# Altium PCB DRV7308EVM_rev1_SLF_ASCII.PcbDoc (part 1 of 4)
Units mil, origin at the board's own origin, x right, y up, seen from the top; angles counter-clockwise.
Board outline 6187 x 6000 mil, 4 copper layers (Top Layer, Ground, Power, Bottom Layer), stack 61.2 mil thick; 306 components, 128 nets, 676 pads, 1026 vias.
Unrouted connection lines stored in the file: 208.
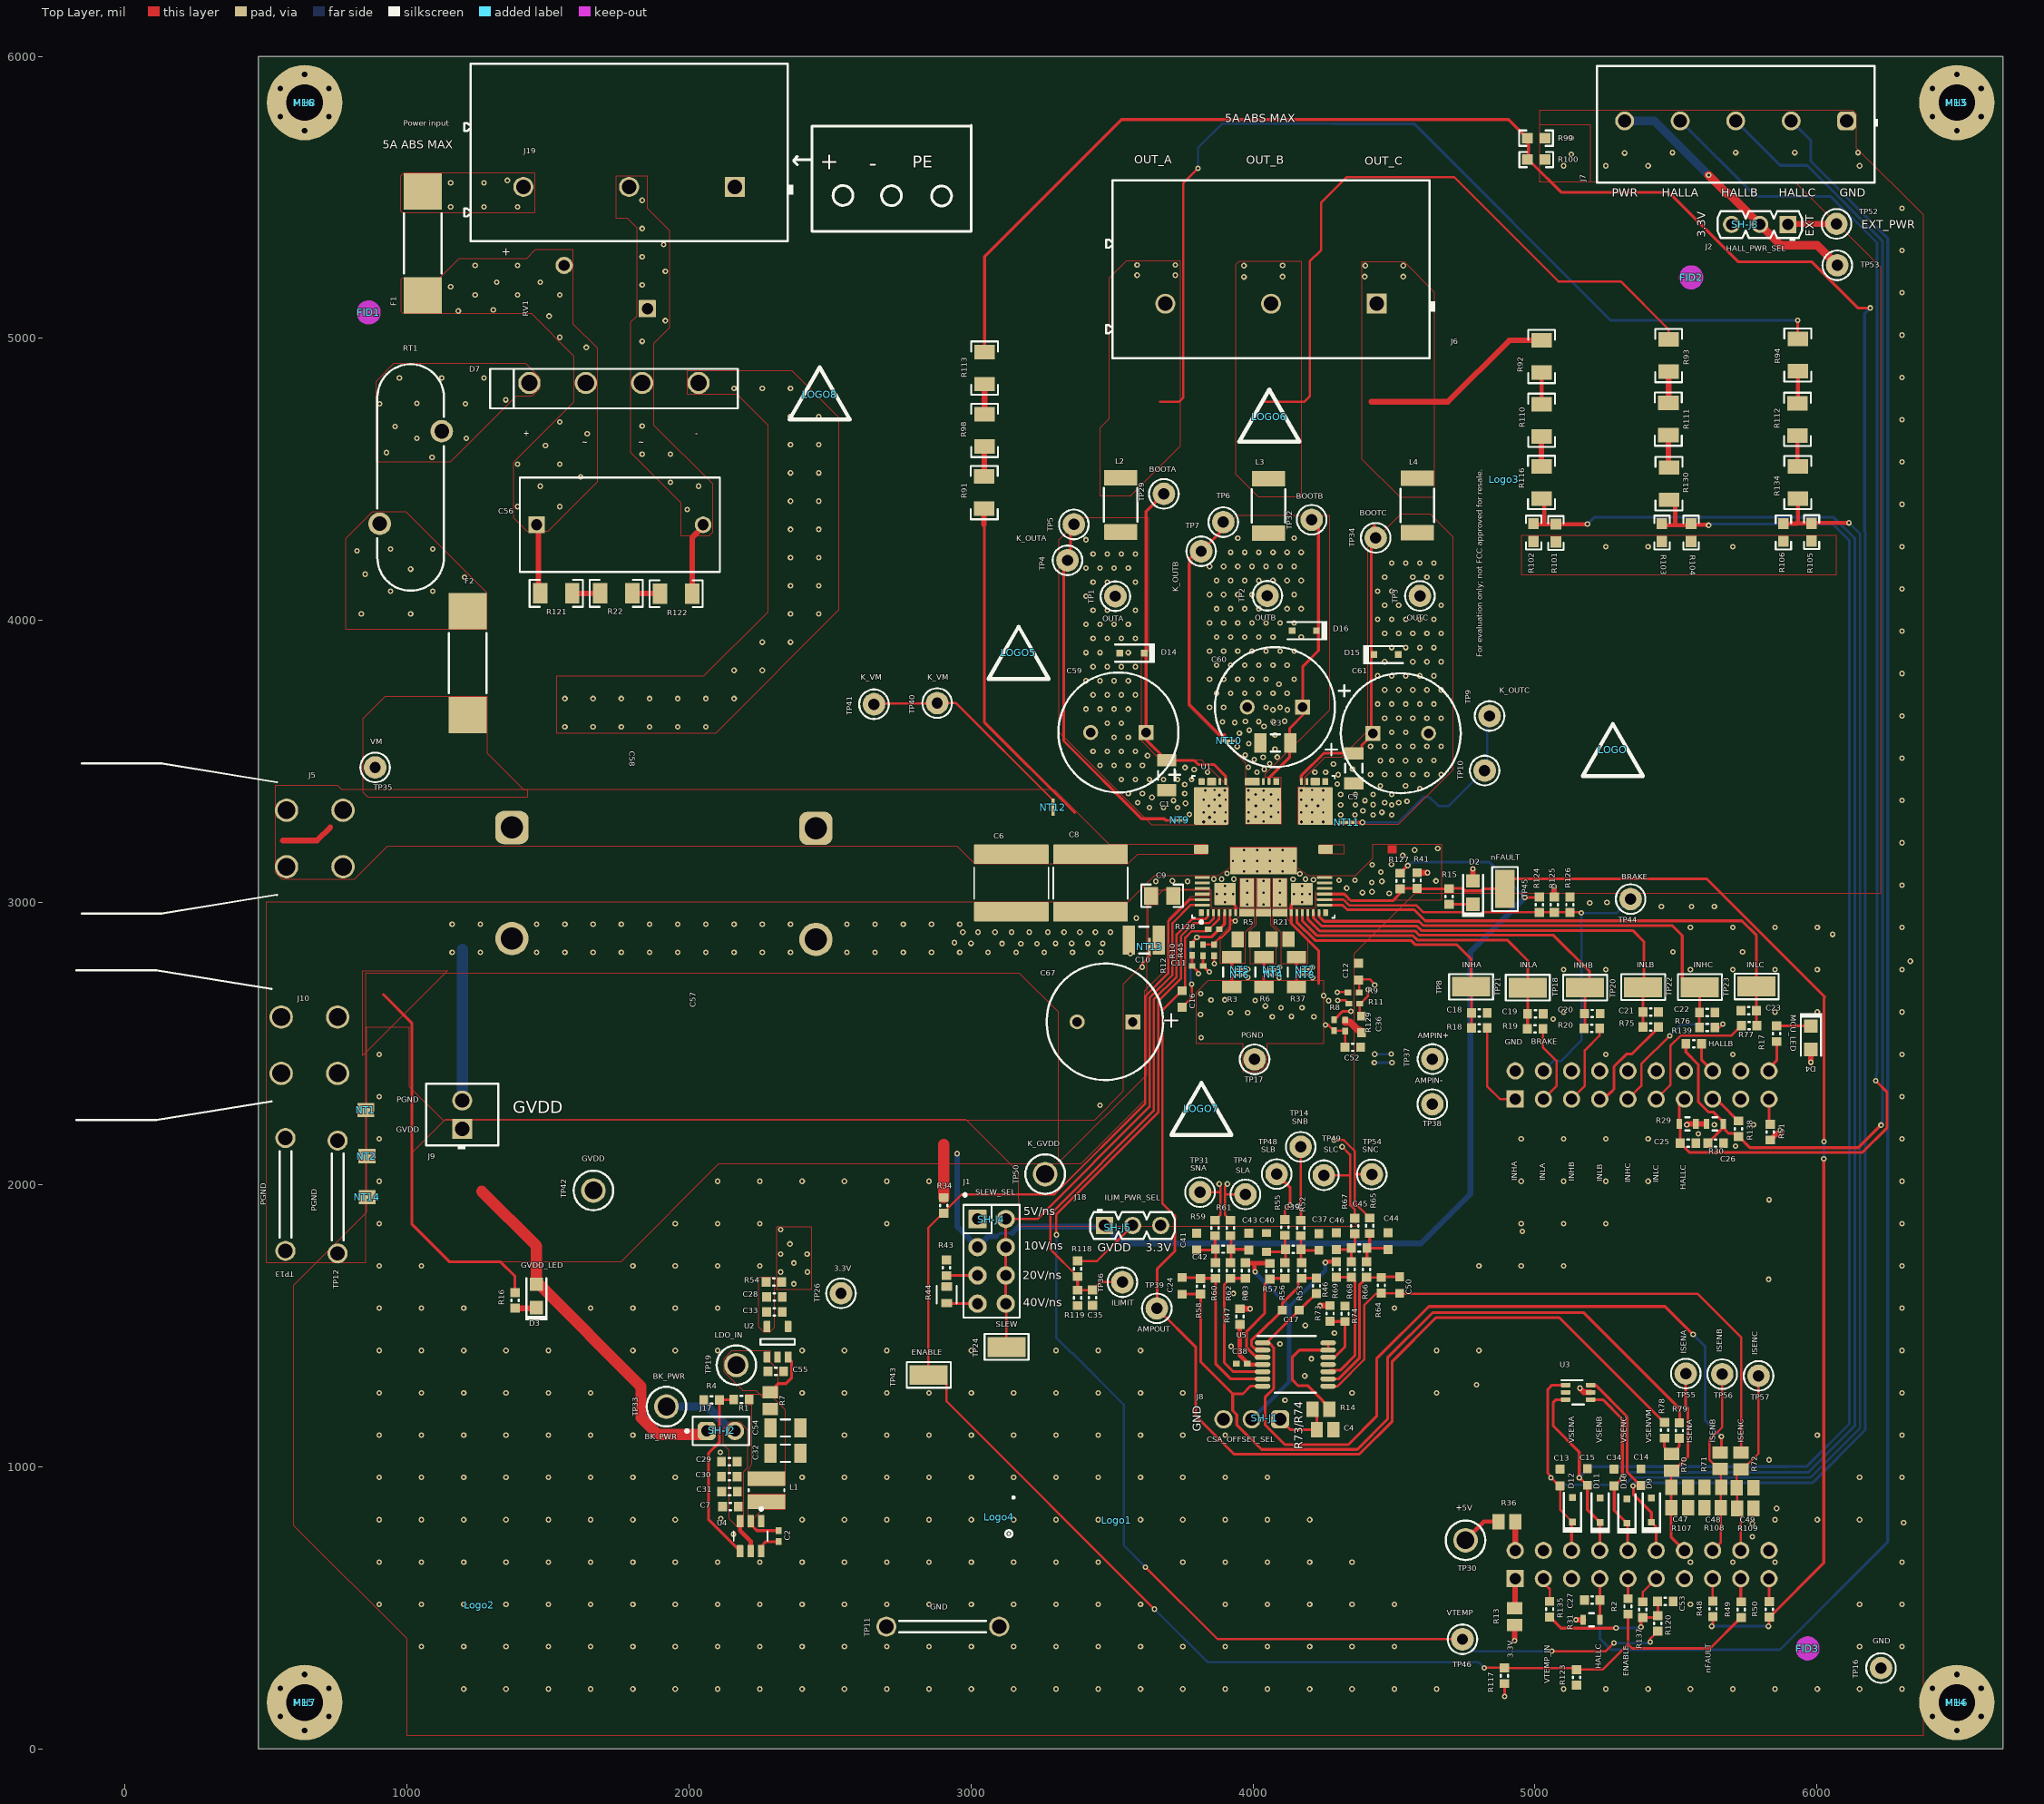
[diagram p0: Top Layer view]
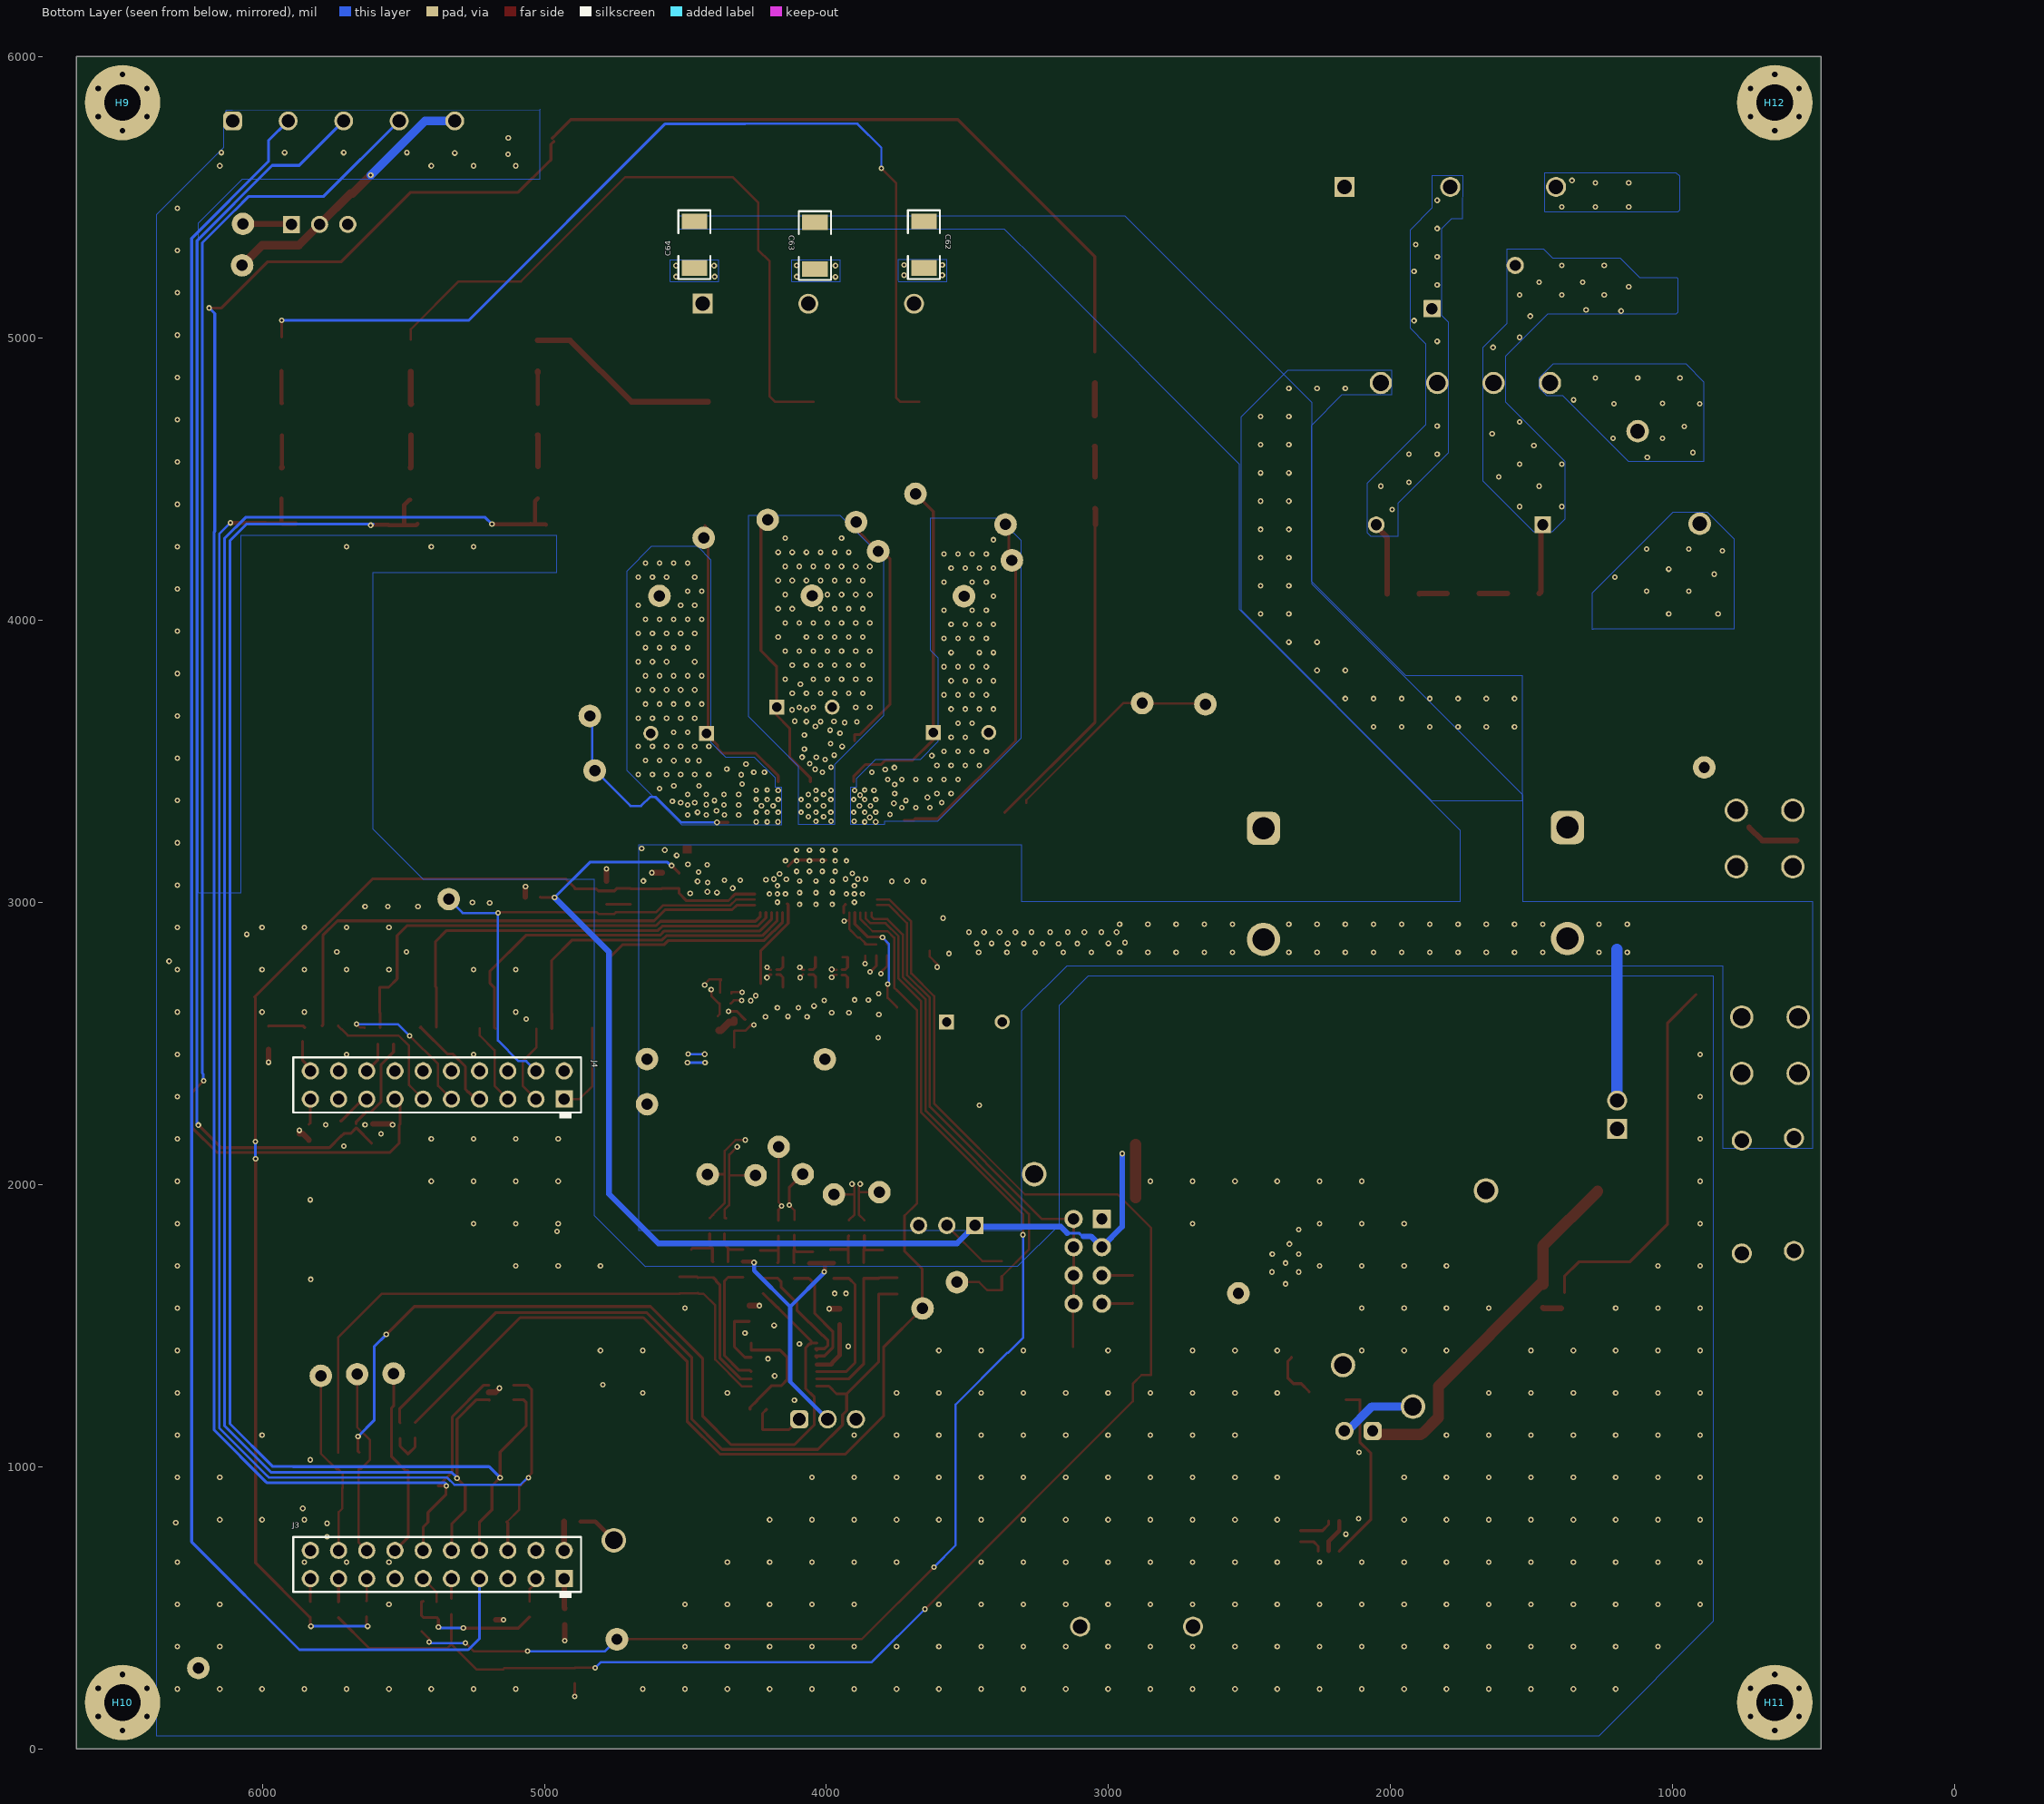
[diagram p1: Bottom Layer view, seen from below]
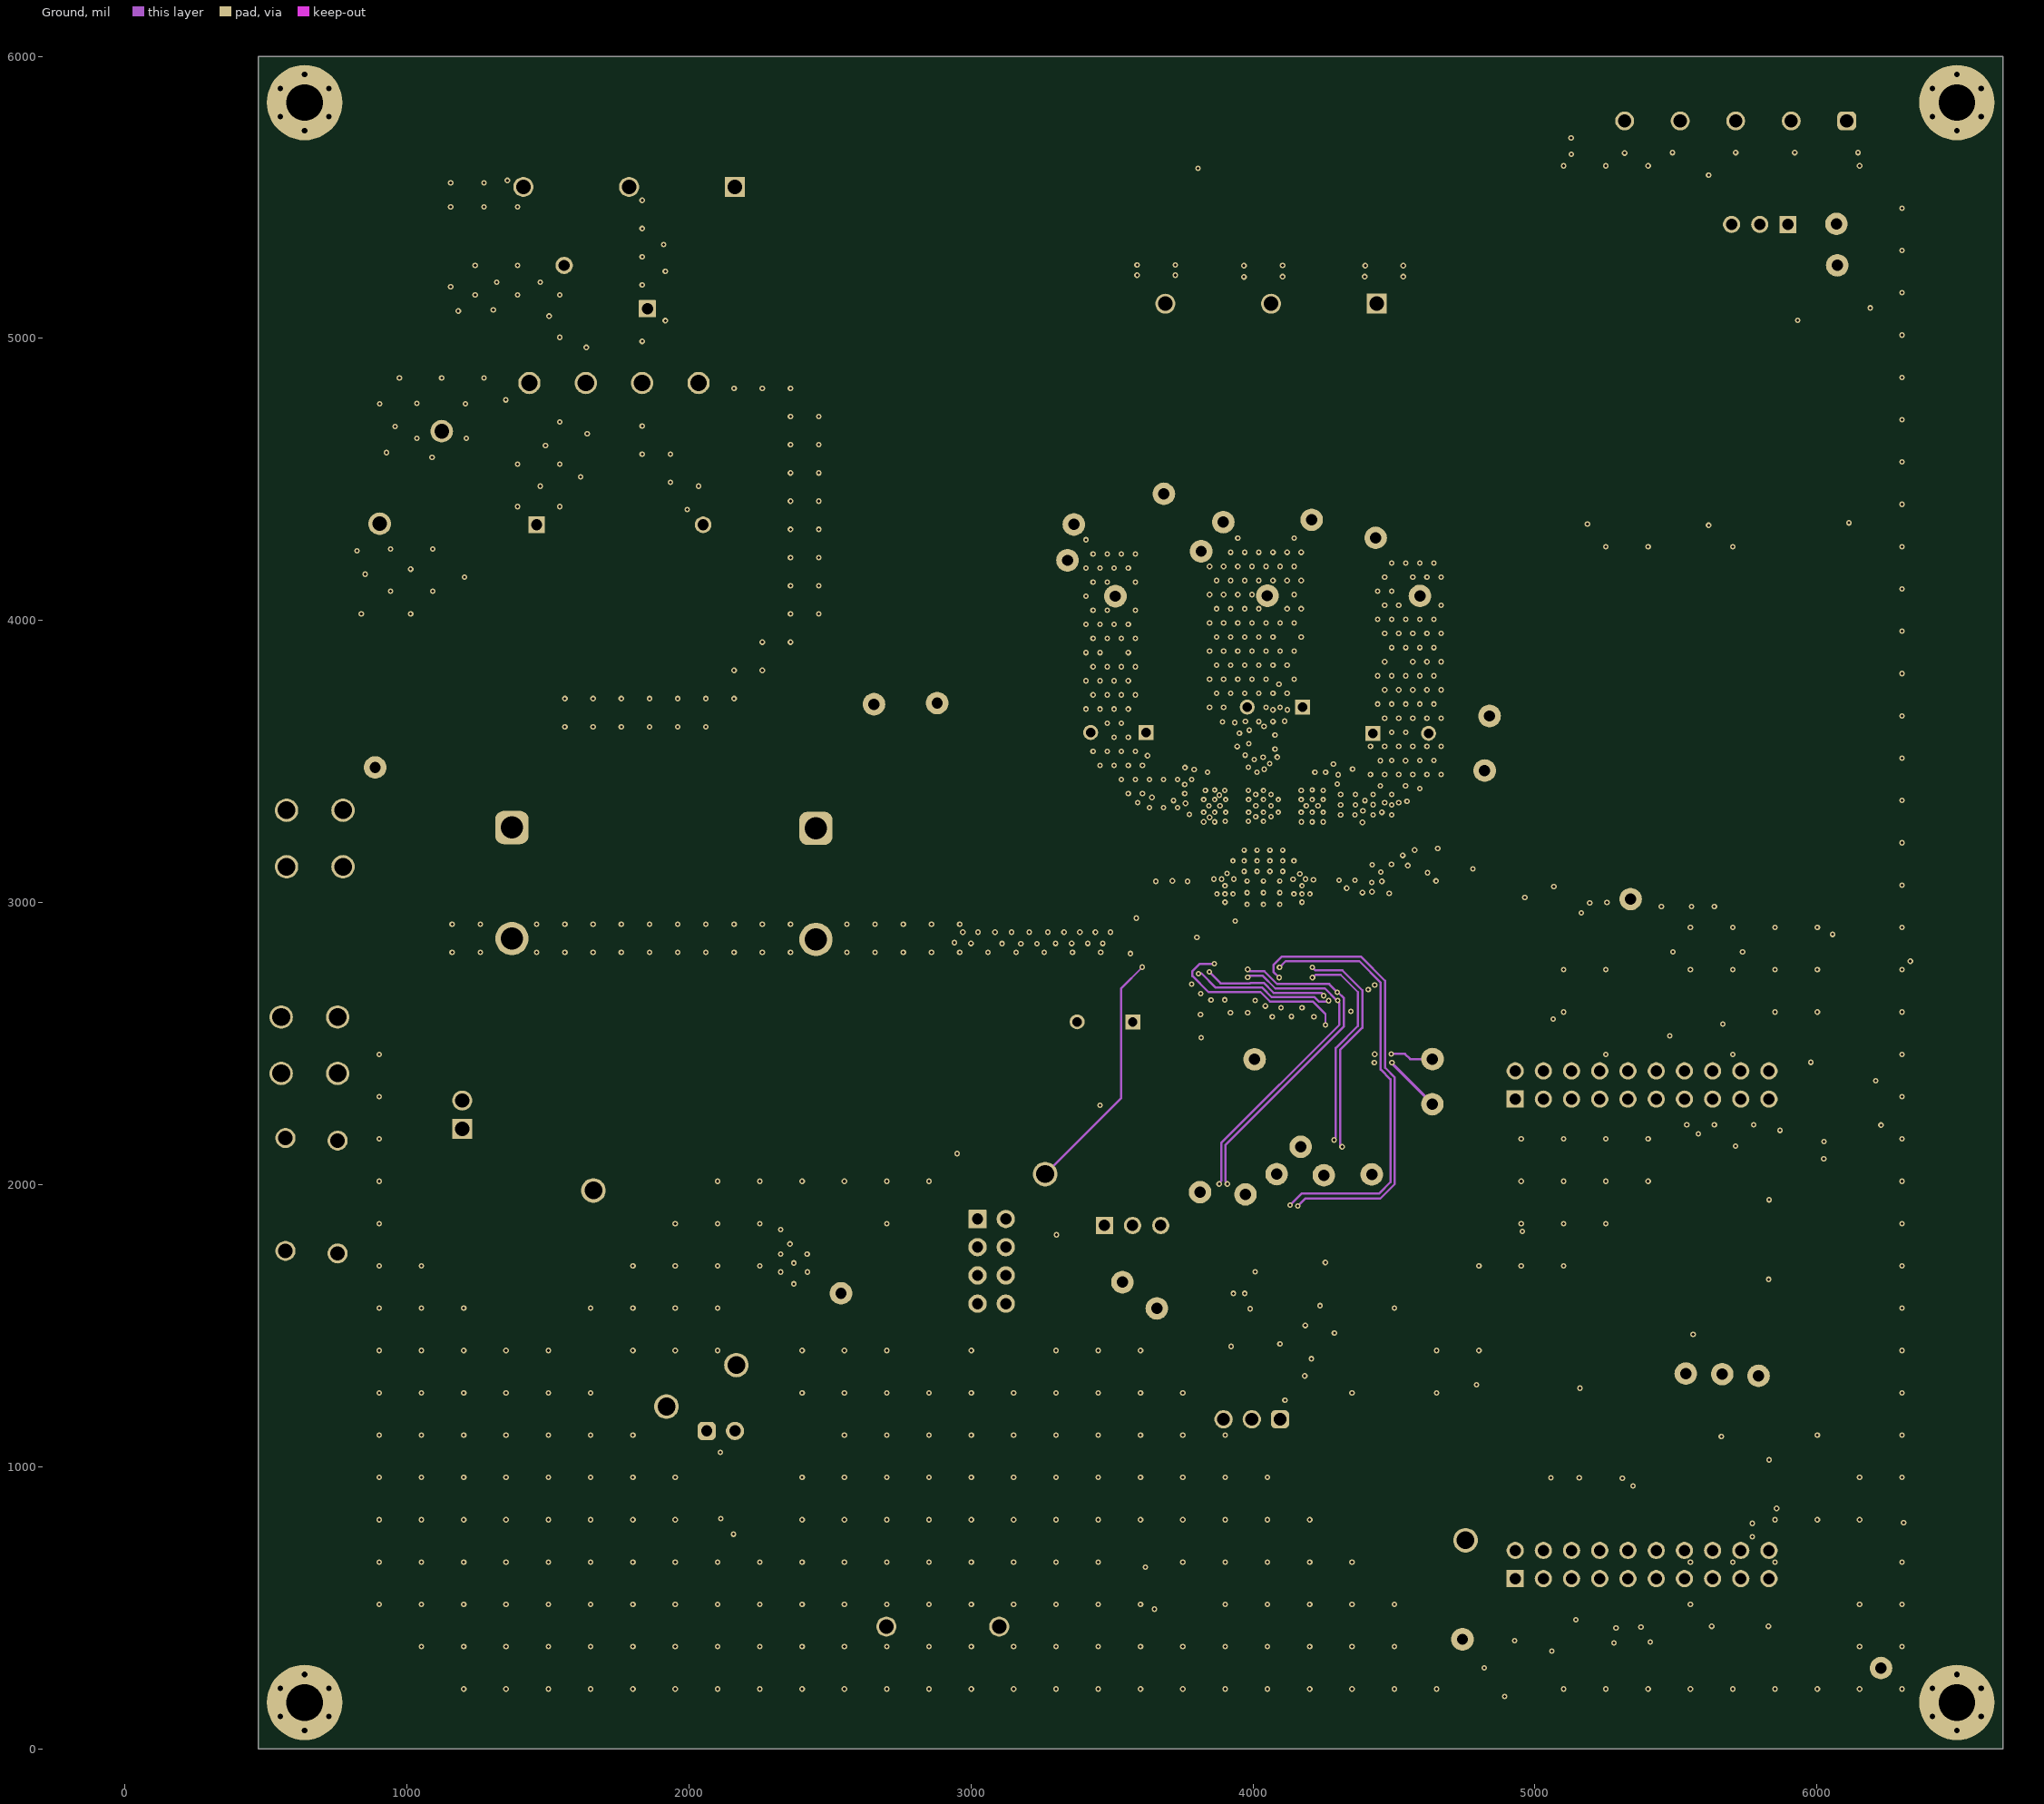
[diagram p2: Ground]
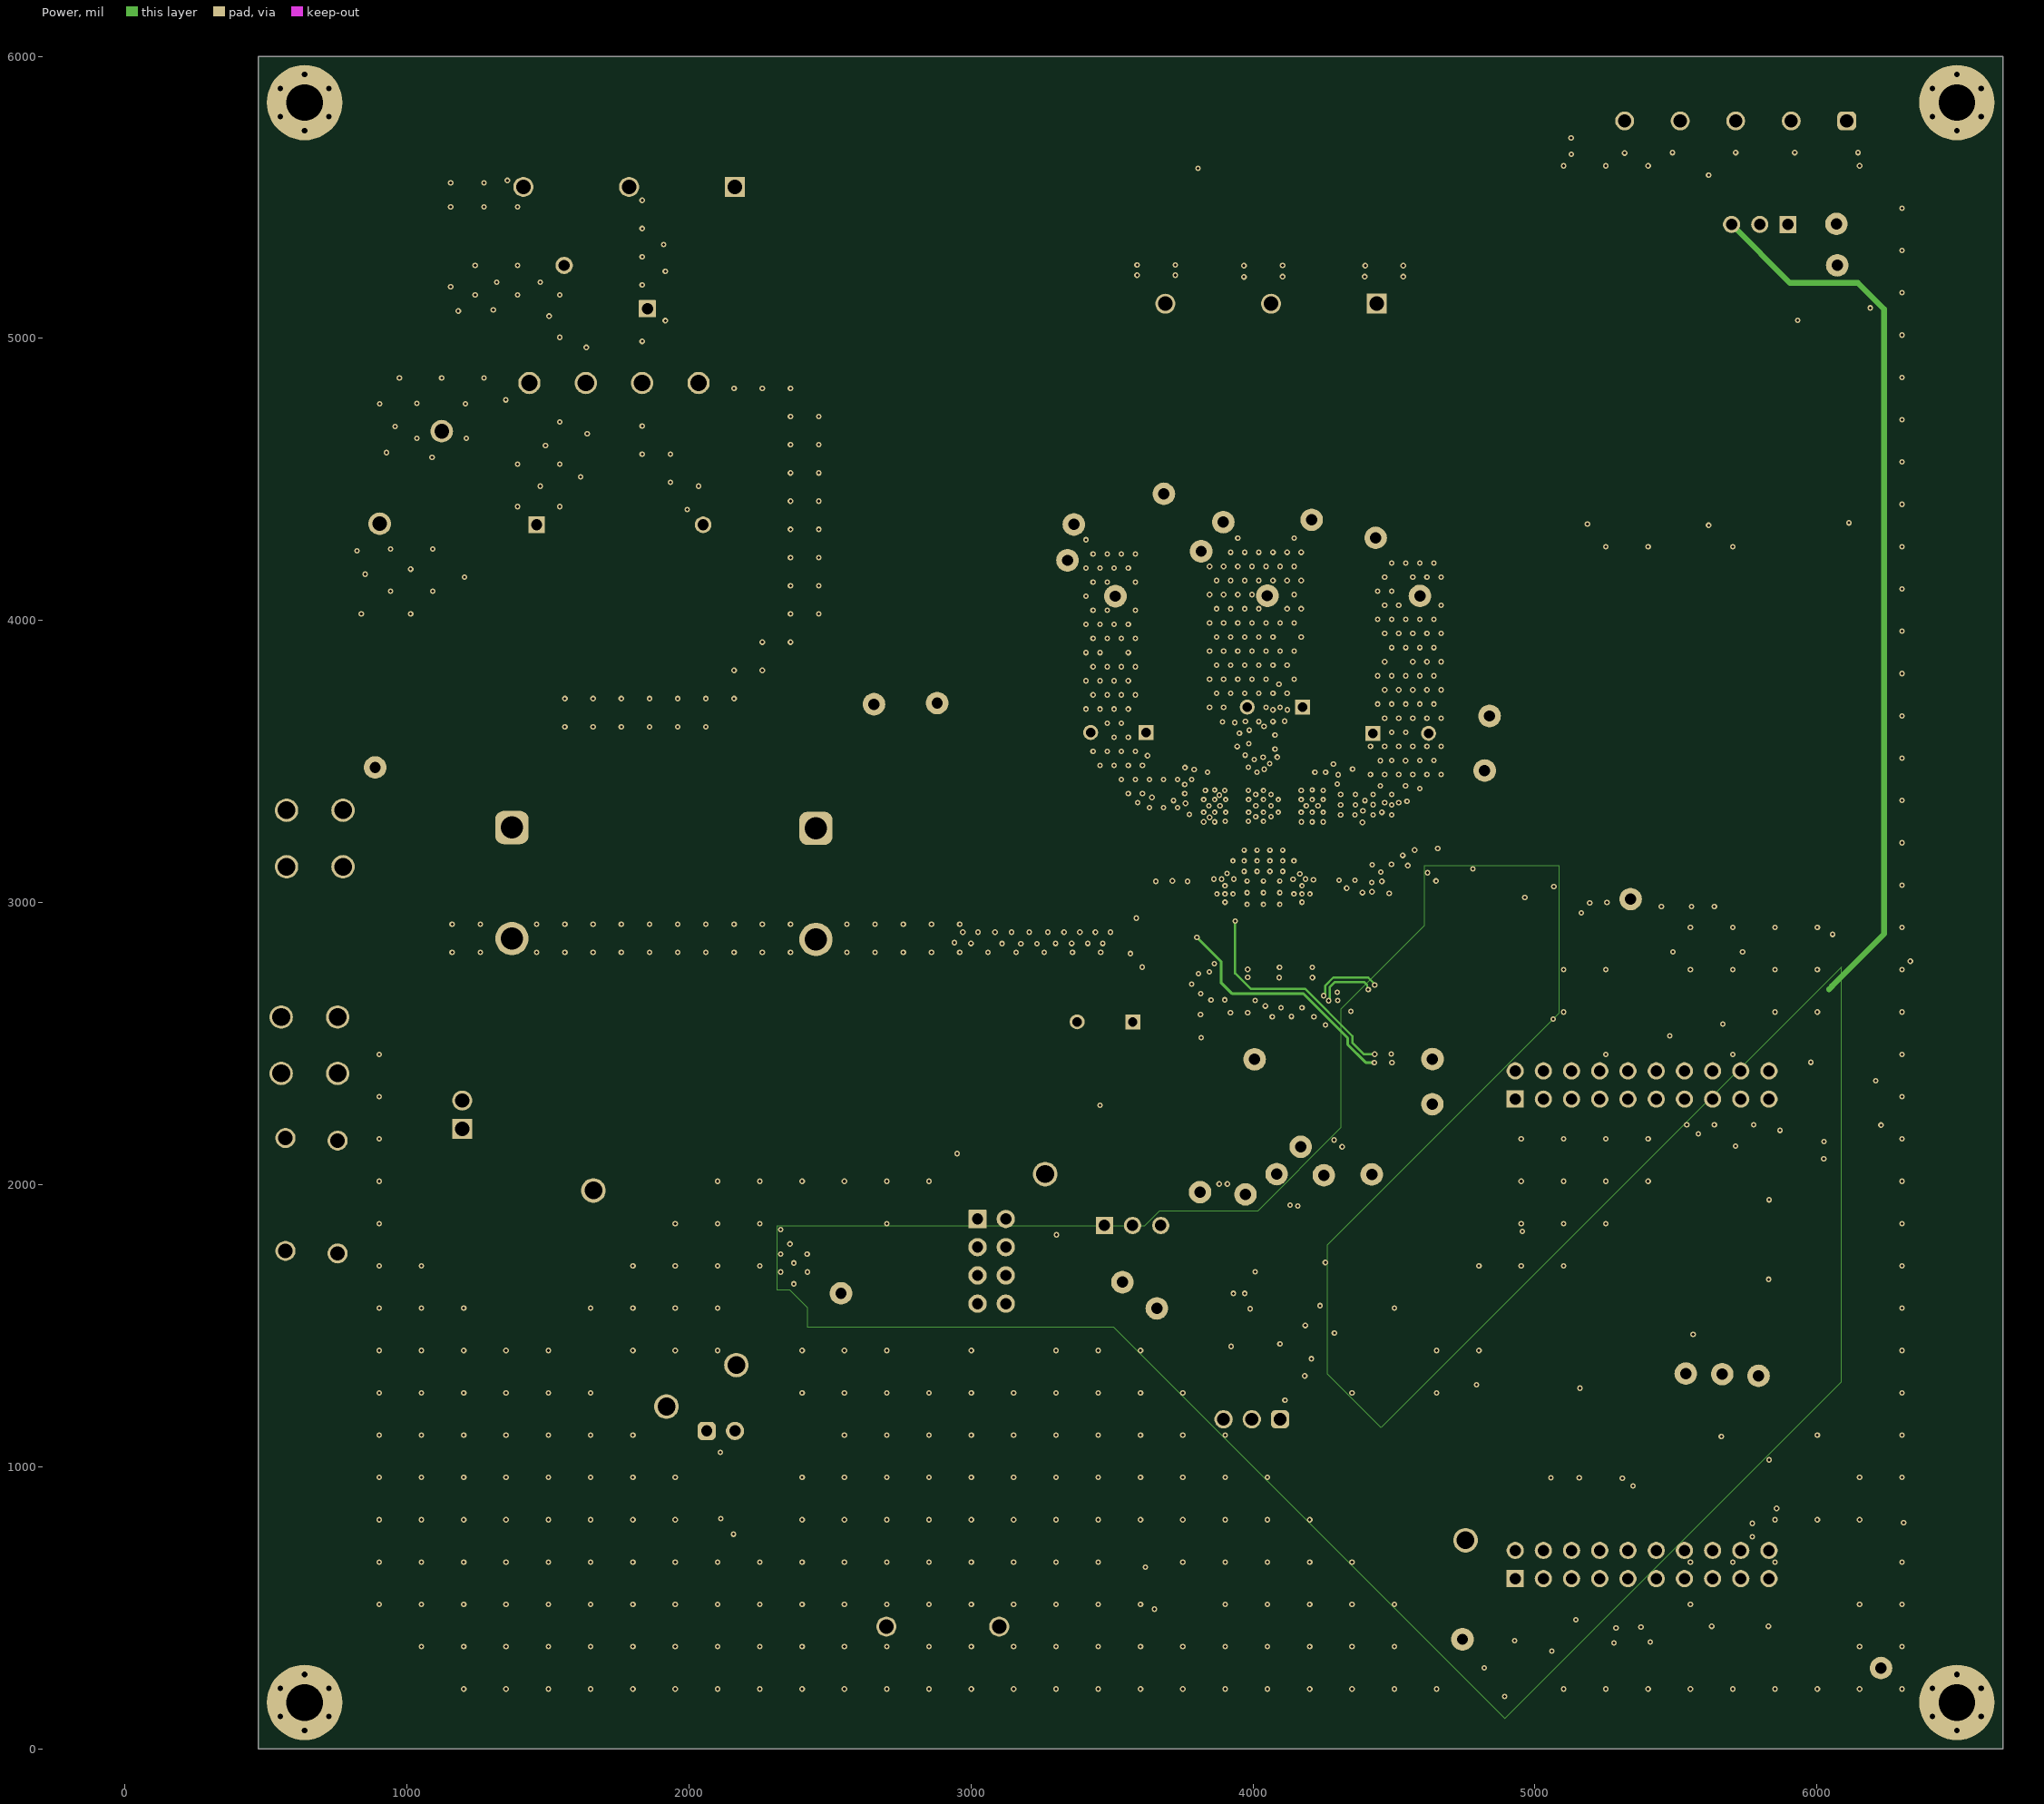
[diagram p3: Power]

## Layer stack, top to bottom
Top Solder: solder mask 0.4, Solder Resist, Dk 3.5
Top Layer: signal copper 4.2
Dielectric 1: prepreg 8, FR-4 High Tg, Dk 4.2
Ground: signal copper 1.4
Dielectric 2: core 34, FR-4 High Tg, Dk 4.2
Power: signal copper 1.4
Dielectric 3: prepreg 8, FR-4 High Tg, Dk 4.2
Bottom Layer: signal copper 4.2
Bottom Solder: solder mask 0.4, Solder Resist, Dk 3.5

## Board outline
473,0 6660,0 6660,6000 473,6000

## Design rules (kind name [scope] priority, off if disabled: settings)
AcuteAngle [All] p0: scope1count=1 scope1_0_kind=Board scope1_0_value=Board scope2count=1 scope2_0_kind=Board scope2_0_value=Board commentlength=0 minimum=4.50000000000000E+0001
AcuteAngle [All] p1: minimum=4.50000000000000E+0001 checktracksonly=FALSE
AssemblyTestPointUsage [All] p0: scope1count=1 scope1_0_kind=Board scope1_0_value=Board scope2count=1 scope2_0_kind=Board scope2_0_value=Board commentlength=0
AssemblyTestPointUsage [All] p1: valid=2
AssemblyTestpoint [All] p0: scope1count=1 scope1_0_kind=Board scope1_0_value=Board scope2count=1 scope2_0_kind=Board scope2_0_value=Board commentlength=0
BoardOutlineClearance [All] p0 off: scope1count=1 scope1_0_kind=Board scope1_0_value=Board scope2count=1 scope2_0_kind=Board scope2_0_value=Board commentlength=172 gap=30 // Protel DXP Scope 1 Expression Was: OnCopper and Not InComponentClass('Logo') and not InComponentClass('FiducialMark') and not InRegion(1000,500,4000,800) and not InPoly
BoardOutlineClearance BoardOutlineClearance_Poly [All] p0 off: scope1count=1 scope1_0_kind=Board scope1_0_value=Board scope2count=1 scope2_0_kind=Board scope2_0_value=Board commentlength=58 gap=25 // Protel DXP Scope 1 Expression Was: OnCopper and IsPoly
BoardOutlineClearance BoardOutlineClearance_MountingHoles [All] p0 off: scope1count=1 scope1_0_kind=Board scope1_0_value=Board scope2count=1 scope2_0_kind=Board scope2_0_value=Board commentlength=86 gap=39.37 // Protel DXP Scope 1 Expression Was: OnCopper and InComponentClass('Mounting Holes')
BoardOutlineClearance BoardOutlineClearance_MountingHoles [OnCopper and InComponentClass('Mounting Holes')] p1: gap=39.37 ignorepadtopadclearanceinfootprint=FALSE
BoardOutlineClearance BoardOutlineClearance_Poly [OnCopper and IsPoly] p2: gap=25 ignorepadtopadclearanceinfootprint=FALSE
BoardOutlineClearance [OnCopper and Not InComponentClass('Logo') and not InComponentClass('FiducialMark') and not InRegion(1000,500,4000,800) and not InPoly] p3: gap=30 ignorepadtopadclearanceinfootprint=FALSE
Clearance Clearance_4 [All] p0: scope1count=1 scope1_0_kind=NetClass scope1_0_value="All Nets" scope2count=1 scope2_0_kind=Layer scope2_0_value=MID1 commentlength=0 gap=7.46
Clearance Clearance_3 [All] p0 off: scope1count=1 scope1_0_kind=Board scope1_0_value=Board scope2count=1 scope2_0_kind=Board scope2_0_value=Board commentlength=76 gap=10 // Protel DXP Scope 1 Expression Was: InNamedPolygon('TOP_LAYER_OUTB_P018')
Clearance Clearance_2 [All] p0: scope1count=1 scope1_0_kind=NetClass scope1_0_value="All Nets" scope2count=1 scope2_0_kind=Layer scope2_0_value=BOTTOM commentlength=0 gap=9
Clearance Clearance_1 [All] p0: scope1count=1 scope1_0_kind=NetClass scope1_0_value="All Nets" scope2count=1 scope2_0_kind=Layer scope2_0_value=MID2 commentlength=0 gap=7.46
Clearance "Stitching AGND" [All] p0 off: scope1count=1 scope1_0_kind=Board scope1_0_value=Board scope2count=1 scope2_0_kind=Board scope2_0_value=Board commentlength=80 gap=70 // Protel DXP Scope 2 Expression Was: (IsVia and (Not IsStitchingVia)) Or IsPad
Clearance [All] p0: scope1count=1 scope1_0_kind=NetClass scope1_0_value="All Nets" scope2count=1 scope2_0_kind=Layer scope2_0_value=TOP commentlength=0 gap=7
Clearance Clearance_FiducialMark [All] p0 off: scope1count=1 scope1_0_kind=Board scope1_0_value=Board scope2count=1 scope2_0_kind=Board scope2_0_value=Board commentlength=81 gap=0 // Protel DXP Scope 2 Expression Was: IsPad and InComponentClass('FiducialMark')
Clearance Clearance_Poly [All] p0 off: scope1count=1 scope1_0_kind=Board scope1_0_value=Board scope2count=1 scope2_0_kind=Board scope2_0_value=Board commentlength=48 gap=5 // Protel DXP Scope 1 Expression Was: InPolygon
Clearance Clearance_Keepouts [All] p0 off: scope1count=1 scope1_0_kind=Board scope1_0_value=Board scope2count=1 scope2_0_kind=Board scope2_0_value=Board commentlength=99 gap=7 // Protel DXP Scope 2 Expression Was: ((IsTrack Or IsArc) And Not InPoly) And IsFree and IsKeepOut
Clearance Clearance_3 [InNamedPolygon('TOP_LAYER_OUTB_P018')] p1: gap=10 ignorepadtopadclearanceinfootprint=TRUE except(0: Arc-Hole Track-Hole SMDPad-Hole THPad-Hole Via-Hole Fill-Hole Poly-Hole Region-Hole Text-Hole)
Clearance "Stitching AGND" [IsStitchingVia and InNet('AGND') vs (IsVia and (Not IsStitchingVia)) Or IsPad] p2: gap=70 ignorepadtopadclearanceinfootprint=TRUE
Clearance Clearance_Keepouts [((IsTrack Or IsArc) And Not InPoly) And IsFree and IsKeepOut vs ((IsTrack Or IsArc) And Not InPoly) And IsFree and IsKeepOut] p3: gap=7 ignorepadtopadclearanceinfootprint=TRUE
Clearance Clearance_Poly [InPolygon] p4: gap=5 ignorepadtopadclearanceinfootprint=TRUE except(7: Fill-Fill Fill-Poly Fill-Region Poly-Poly Poly-Region Region-Region)
Clearance Clearance_FiducialMark [IsKeepOut and InComponentClass('FiducialMark') vs IsPad and InComponentClass('FiducialMark')] p5: gap=0 ignorepadtopadclearanceinfootprint=FALSE
Clearance [InNetClass('All Nets') vs OnLayer('Top Layer')] p6: gap=7 ignorepadtopadclearanceinfootprint=TRUE
Clearance Clearance_2 [InNetClass('All Nets') vs OnLayer('Bottom Layer')] p7: gap=9 ignorepadtopadclearanceinfootprint=TRUE
Clearance Clearance_1 [InNetClass('All Nets') vs OnLayer('Power')] p8: gap=7.46 ignorepadtopadclearanceinfootprint=TRUE
Clearance Clearance_4 [InNetClass('All Nets') vs OnLayer('Ground')] p9: gap=7.46 ignorepadtopadclearanceinfootprint=TRUE
ComponentClearance ComponentClearance_NT [All] p0 off: scope1count=1 scope1_0_kind=Board scope1_0_value=Board scope2count=1 scope2_0_kind=Component scope2_0_value="No Component" commentlength=169 gap=0 collisioncheckmode=3 // Protel DXP Scope 1 Expression Was: (InComponent('NT1') OR InComponent('NT2') OR InComponent('NT3') OR InComponent('NT4') OR InComponent('NT5') OR InComponent('NT6'))
ComponentClearance [All] p0: scope1count=1 scope1_0_kind=Board scope1_0_value=Board scope2count=1 scope2_0_kind=Board scope2_0_value=Board commentlength=0 gap=30 collisioncheckmode=3
ComponentClearance ComponentClearance_THtoTH [All] p0 off: scope1count=1 scope1_0_kind=Board scope1_0_value=Board scope2count=1 scope2_0_kind=Board scope2_0_value=Board commentlength=54 gap=30 collisioncheckmode=3 // Protel DXP Scope 2 Expression Was: IsThruComponent
ComponentClearance ComponentClearance_THtoSMT [All] p0 off: scope1count=1 scope1_0_kind=Board scope1_0_value=Board scope2count=1 scope2_0_kind=Board scope2_0_value=Board commentlength=53 gap=40 collisioncheckmode=3 // Protel DXP Scope 2 Expression Was: IsSMTComponent
ComponentClearance ComponentClearance_SmallPassives [All] p0 off: scope1count=1 scope1_0_kind=Board scope1_0_value=Board scope2count=1 scope2_0_kind=Board scope2_0_value=Board commentlength=508 gap=14.96 collisioncheckmode=3 // Protel DXP Scope 2 Expression Was: HasFootprint('0201*') or HasFootprint('0402*') or HasFootprint('0508') or HasFootprint('0603*') or HasFootprint('0612') or HasFootprint('0805*') or HasFootprint('0815*') or HasFootprint('0830*') or HasFootprint('1206*') or HasFootprint('1210*') or HasFootprint('1808*') or HasFootprint('1812*') or HasFootprint('1825*') or HasFootprint('2010*') or HasFootprint('2220*') or HasFootprint('2225*') or HasFootprint('2512*') or HasFootprint('2728*') or HasFootprint('3518*')
ComponentClearance ComponentClearance_MountingHoles [All] p0: scope1count=1 scope1_0_kind=ComponentClass scope1_0_value="Mounting Holes" scope2count=1 scope2_0_kind=Board scope2_0_value=Board commentlength=0 gap=250 collisioncheckmode=3
ComponentClearance ComponentClearance_ScrewToNut [All] p0 off: scope1count=1 scope1_0_kind=Board scope1_0_value=Board scope2count=1 scope2_0_kind=Board scope2_0_value=Board commentlength=71 gap=5 collisioncheckmode=3 // Protel DXP Scope 2 Expression Was: (HasFootprint('Keystone_1902C'))
ComponentClearance ComponentClearance_Logo [All] p0: scope1count=1 scope1_0_kind=ComponentClass scope1_0_value=Logo scope2count=1 scope2_0_kind=Board scope2_0_value=Board commentlength=0 gap=50 collisioncheckmode=3
ComponentClearance ComponentClearance_Shunt [All] p0: scope1count=1 scope1_0_kind=ComponentClass scope1_0_value=Header scope2count=1 scope2_0_kind=ComponentClass scope2_0_value=Shunt commentlength=0 gap=0 collisioncheckmode=3
ComponentClearance ComponentClearance_MountingHoles_FiducialMarks [All] p0: scope1count=1 scope1_0_kind=ComponentClass scope1_0_value="Mounting Holes" scope2count=1 scope2_0_kind=ComponentClass scope2_0_value=FiducialMark commentlength=0 gap=50 collisioncheckmode=3
ComponentClearance ComponentClearance_MountingHoles_FiducialMarks [InComponentClass('Mounting Holes') vs InComponentClass('FiducialMark')] p1: gap=50 collisioncheckmode=3 verticalgap=10 showdistances=FALSE
ComponentClearance ComponentClearance_Shunt [InComponentClass('Header') vs InComponentClass('Shunt')] p2: gap=0 collisioncheckmode=3 verticalgap=0 showdistances=FALSE
ComponentClearance ComponentClearance_Logo [InComponentClass('Logo')] p3: gap=50 collisioncheckmode=3 verticalgap=10 showdistances=FALSE
ComponentClearance ComponentClearance_ScrewToNut [(HasFootprint('NY PMS 440 0025 PH')) vs (HasFootprint('Keystone_1902C'))] p4: gap=5 collisioncheckmode=3 verticalgap=10 showdistances=FALSE
ComponentClearance ComponentClearance_MountingHoles [InComponentClass('Mounting Holes')] p5: gap=250 collisioncheckmode=3 verticalgap=100000 showdistances=FALSE
ComponentClearance ComponentClearance_SmallPassives [HasFootprint('0201*') or HasFootprint('0402*') or HasFootprint('0508') or HasFootprint('0603*') or HasFootprint('0612') or HasFootprint('0805*') or HasFootprint('0815*') or HasFootprint('0830*') or HasFootprint('1206*') or HasFootprint('1210*') or HasFootprint('1808*') or HasFootprint('1812*') or HasFootprint('1825*') or HasFootprint('2010*') or HasFootprint('2220*') or HasFootprint('2225*') or HasFootprint('2512*') or HasFootprint('2728*') or HasFootprint('3518*') vs HasFootprint('0201*') or HasFootprint('0402*') or HasFootprint('0508') or HasFootprint('0603*') or HasFootprint('0612') or HasFootprint('0805*') or HasFootprint('0815*') or HasFootprint('0830*') or HasFootprint('1206*') or HasFootprint('1210*') or HasFootprint('1808*') or HasFootprint('1812*') or HasFootprint('1825*') or HasFootprint('2010*') or HasFootprint('2220*') or HasFootprint('2225*') or HasFootprint('2512*') or HasFootprint('2728*') or HasFootprint('3518*')] p6: gap=14.96 collisioncheckmode=3 verticalgap=10 showdistances=FALSE
ComponentClearance ComponentClearance_THtoSMT [IsThruComponent vs IsSMTComponent] p7: gap=40 collisioncheckmode=3 verticalgap=30 showdistances=FALSE
ComponentClearance ComponentClearance_THtoTH [IsThruComponent vs IsThruComponent] p8: gap=30 collisioncheckmode=3 verticalgap=30 showdistances=FALSE
ComponentClearance [All] p9: gap=30 collisioncheckmode=3 verticalgap=10 showdistances=FALSE
ComponentClearance ComponentClearance_NT [(InComponent('NT1') OR InComponent('NT2') OR InComponent('NT3') OR InComponent('NT4') OR InComponent('NT5') OR InComponent('NT6')) vs InComponent('No Component')] p10: gap=0 collisioncheckmode=3 verticalgap=10 showdistances=FALSE
DiffPairsRouting [All] p0: scope1count=1 scope1_0_kind=Board scope1_0_value=Board scope2count=1 scope2_0_kind=Board scope2_0_value=Board commentlength=0
DiffPairsRouting [All] p1: maxlimit=100 minlimit=10 mostfreqgap=10 toplayer_minwidth=15 toplayer_maxwidth=15 toplayer_prefwidth=15 midlayer1_minwidth=15 midlayer1_maxwidth=15 midlayer1_prefwidth=15 midlayer2_minwidth=15 midlayer2_maxwidth=15 midlayer2_prefwidth=15 bottomlayer_minwidth=15 bottomlayer_maxwidth=15 bottomlayer_prefwidth=15 maxuncoupledlength=1000
FabricationTestPointUsage TestPointUsage [All] p0: scope1count=1 scope1_0_kind=Board scope1_0_value=Board scope2count=1 scope2_0_kind=Board scope2_0_value=Board commentlength=0 valid=2 allowmultiple=FALSE
FabricationTestPointUsage TestPointUsage [All] p1: valid=2 allowmultiple=FALSE
FabricationTestpoint Testpoint [All] p0: scope1count=1 scope1_0_kind=Board scope1_0_value=Board scope2count=1 scope2_0_kind=Board scope2_0_value=Board commentlength=0 side=3 testpointundercomponent=TRUE minsize=40 maxsize=100 preferedsize=60 minholesize=0 maxholesize=40 preferedholesize=32 testpointgrid=1
FabricationTestpoint Testpoint [All] p1: side=3 testpointundercomponent=TRUE minsize=40 maxsize=100 preferedsize=60 minholesize=0 maxholesize=40 preferedholesize=32 testpointgrid=1 allowsidetop=TRUE allowsidebottom=TRUE usegrid=TRUE gridtolerance=0.01
FanoutControl Fanout_Small [All] p0 off: scope1count=1 scope1_0_kind=Board scope1_0_value=Board scope2count=1 scope2_0_kind=Board scope2_0_value=Board commentlength=84 // Protel DXP Scope 1 Expression Was: (CompPinCount < 5)   Fanout_Small (Default Rule)
FanoutControl Fanout_Default [All] p0: scope1count=1 scope1_0_kind=Board scope1_0_value=Board scope2count=1 scope2_0_kind=Board scope2_0_value=Board commentlength=30 // Fanout_Default (Default Rule)
FanoutControl Fanout_SOIC [All] p0 off: scope1count=1 scope1_0_kind=Board scope1_0_value=Board scope2count=1 scope2_0_kind=Board scope2_0_value=Board commentlength=71 // Protel DXP Scope 1 Expression Was: IsSOIC   Fanout_SOIC (Default Rule)
FanoutControl Fanout_BGA [All] p0 off: scope1count=1 scope1_0_kind=Board scope1_0_value=Board scope2count=1 scope2_0_kind=Board scope2_0_value=Board commentlength=69 // Protel DXP Scope 1 Expression Was: IsBGA   Fanout_BGA (Default Rule)
FanoutControl Fanout_LCC [All] p0 off: scope1count=1 scope1_0_kind=Board scope1_0_value=Board scope2count=1 scope2_0_kind=Board scope2_0_value=Board commentlength=69 // Protel DXP Scope 1 Expression Was: IsLCC   Fanout_LCC (Default Rule)
FanoutControl Fanout_LCC [IsLCC] p1: bgadir=Out bgaviamode=Centered fanoutstyle=Auto fanoutdirection=Alternating viagrid=1 // Fanout_LCC (Default Rule)
FanoutControl Fanout_BGA [IsBGA] p2: bgadir=Out bgaviamode=Centered fanoutstyle=Auto fanoutdirection=Alternating viagrid=1 // Fanout_BGA (Default Rule)
FanoutControl Fanout_Default [All] p4: bgadir=Out bgaviamode=Centered fanoutstyle=Auto fanoutdirection=Alternating viagrid=1 // Fanout_Default (Default Rule)
FanoutControl Fanout_Small [(CompPinCount < 5)] p5: bgadir=Out bgaviamode=Centered fanoutstyle=Auto fanoutdirection=OutThenIn viagrid=1 // Fanout_Small (Default Rule)
Height [All] p0: scope1count=1 scope1_0_kind=Board scope1_0_value=Board scope2count=1 scope2_0_kind=Board scope2_0_value=Board commentlength=0
Height [All] p1: minheight=0 maxheight=1270 prefheight=500
HoleSize [All] p0: scope1count=1 scope1_0_kind=Board scope1_0_value=Board scope2count=1 scope2_0_kind=Board scope2_0_value=Board commentlength=0 absolutevalues=TRUE maxlimit=270 minlimit=1 maxpercent=80.000 minpercent=20.000
HoleSize [All] p1: absolutevalues=TRUE maxlimit=270 minlimit=1 maxpercent=80.000 minpercent=20.000
HoleToHoleClearance [All] p0: scope1count=1 scope1_0_kind=Board scope1_0_value=Board scope2count=1 scope2_0_kind=Board scope2_0_value=Board commentlength=0
LayerPairs [All] p0: scope1count=1 scope1_0_kind=Board scope1_0_value=Board scope2count=1 scope2_0_kind=Board scope2_0_value=Board commentlength=0 enforce=TRUE
MinimumAnnularRing [All] p0: scope1count=1 scope1_0_kind=Board scope1_0_value=Board scope2count=1 scope2_0_kind=Board scope2_0_value=Board commentlength=0 minimumring=5
MinimumAnnularRing MinimumAnnularRing_ThermalPadVias [All] p0 off: scope1count=1 scope1_0_kind=Board scope1_0_value=Board scope2count=1 scope2_0_kind=Board scope2_0_value=Board commentlength=63 minimumring=5 // Protel DXP Scope 1 Expression Was: IsVia and InAnyComponent
MinimumAnnularRing MinimumAnnularRing_ThermalPadVias [IsVia and InAnyComponent] p1: minimumring=5
MinimumAnnularRing [All] p2: minimumring=5
MinimumSolderMaskSliver [All] p0: scope1count=1 scope1_0_kind=Board scope1_0_value=Board scope2count=1 scope2_0_kind=Board scope2_0_value=Board commentlength=0
MinimumSolderMaskSliver MinimumSolderMaskSliver_Logo [All] p0: scope1count=1 scope1_0_kind=ComponentClass scope1_0_value=Logo scope2count=1 scope2_0_kind=ComponentClass scope2_0_value=Logo commentlength=0
MinimumSolderMaskSliver MinimumSolderMaskSliver_Logo [InComponentClass('Logo') vs InComponentClass('Logo')] p1: minsoldermaskwidth=0.7
MinimumSolderMaskSliver [All] p2: minsoldermaskwidth=1
NetAntennae [All] p0: scope1count=1 scope1_0_kind=Board scope1_0_value=Board scope2count=1 scope2_0_kind=Board scope2_0_value=Board commentlength=0
PasteMaskExpansion [All] p0: scope1count=1 scope1_0_kind=Board scope1_0_value=Board scope2count=1 scope2_0_kind=Board scope2_0_value=Board commentlength=0 expansion=0
PlaneClearance [All] p0: scope1count=1 scope1_0_kind=Board scope1_0_value=Board scope2count=1 scope2_0_kind=Board scope2_0_value=Board commentlength=0 clearance=20
PlaneConnect [All] p0: scope1count=1 scope1_0_kind=Board scope1_0_value=Board scope2count=1 scope2_0_kind=Board scope2_0_value=Board commentlength=0 planeconnectstyle=Direct reliefexpansion=10 reliefentries=4 reliefconductorwidth=10 reliefairgap=10
PlaneConnect [All] p1: planeconnectstyle=Direct reliefexpansion=10 reliefentries=4 reliefconductorwidth=10 reliefairgap=10
PolygonConnect "direct connect OUTB" [All] p0 off: scope1count=1 scope1_0_kind=Board scope1_0_value=Board scope2count=1 scope2_0_kind=Board scope2_0_value=Board commentlength=76 connectstyle=Direct reliefconductorwidth=10 reliefentries=4 polygonreliefangle="90 Angle" // Protel DXP Scope 2 Expression Was: IsNamedPolygon('TOP_LAYER_OUTB_P018')
PolygonConnect OUTB_POLY [All] p0 off: scope1count=1 scope1_0_kind=Board scope1_0_value=Board scope2count=1 scope2_0_kind=Board scope2_0_value=Board commentlength=76 connectstyle=Direct reliefconductorwidth=10 reliefentries=4 polygonreliefangle="90 Angle" // Protel DXP Scope 2 Expression Was: IsNamedPolygon('TOP_LAYER_OUTB_P018')
PolygonConnect PolygonConnect_1 [All] p0 off: scope1count=1 scope1_0_kind=Board scope1_0_value=Board scope2count=1 scope2_0_kind=Board scope2_0_value=Board commentlength=76 connectstyle=Direct reliefconductorwidth=10 reliefentries=4 polygonreliefangle="90 Angle" // Protel DXP Scope 2 Expression Was: IsNamedPolygon('TOP_LAYER_OUTB_P018')
PolygonConnect [All] p0: scope1count=1 scope1_0_kind=Board scope1_0_value=Board scope2count=1 scope2_0_kind=Board scope2_0_value=Board commentlength=0 connectstyle=Direct reliefconductorwidth=10 reliefentries=4 polygonreliefangle="90 Angle"
PolygonConnect "direct connect OUTB" [All vs IsNamedPolygon('TOP_LAYER_OUTB_P018')] p1: connectstyle=Direct reliefconductorwidth=10 reliefentries=4 polygonreliefangle="90 Angle" airgapwidth=10
PolygonConnect OUTB_POLY [All vs IsNamedPolygon('TOP_LAYER_OUTB_P018')] p2: connectstyle=Direct reliefconductorwidth=10 reliefentries=4 polygonreliefangle="90 Angle" airgapwidth=10
PolygonConnect PolygonConnect_1 [All vs IsNamedPolygon('TOP_LAYER_OUTB_P018')] p3: connectstyle=Direct reliefconductorwidth=10 reliefentries=4 polygonreliefangle="90 Angle" airgapwidth=10
PolygonConnect [All] p4: connectstyle=Direct reliefconductorwidth=10 reliefentries=4 polygonreliefangle="90 Angle" airgapwidth=10
RoutingCorners [All] p0: scope1count=1 scope1_0_kind=Board scope1_0_value=Board scope2count=1 scope2_0_kind=Board scope2_0_value=Board commentlength=0 cornerstyle=45-Degree minsetback=100 maxsetback=100
RoutingLayers [All] p0: scope1count=1 scope1_0_kind=Board scope1_0_value=Board scope2count=1 scope2_0_kind=Board scope2_0_value=Board commentlength=0 top layer=Automatic mid layer 1=Automatic mid layer 2=Automatic bottom layer=Automatic
RoutingPriority [All] p0: scope1count=1 scope1_0_kind=Board scope1_0_value=Board scope2count=1 scope2_0_kind=Board scope2_0_value=Board commentlength=0
RoutingTopology [All] p0: scope1count=1 scope1_0_kind=Board scope1_0_value=Board scope2count=1 scope2_0_kind=Board scope2_0_value=Board commentlength=0 topology=Shortest
RoutingVias [All] p0: scope1count=1 scope1_0_kind=Board scope1_0_value=Board scope2count=1 scope2_0_kind=Board scope2_0_value=Board commentlength=0 holewidth=10 width=25 viastyle="Through Hole" minholewidth=10 minwidth=20 maxholewidth=10 maxwidth=30
RoutingVias ThermalPadVias [All] p0 off: scope1count=1 scope1_0_kind=Board scope1_0_value=Board scope2count=1 scope2_0_kind=Board scope2_0_value=Board commentlength=63 holewidth=7.87 width=19.68 viastyle="Through Hole" minholewidth=7.87 minwidth=19.68 maxholewidth=30 maxwidth=50 // Protel DXP Scope 1 Expression Was: IsVia and InAnyComponent
RoutingVias ThermalPadVias [IsVia and InAnyComponent] p1: holewidth=7.87 width=19.68 viastyle="Through Hole" minholewidth=7.87 minwidth=19.68 maxholewidth=30 maxwidth=50
RoutingVias [All] p2: holewidth=10 width=25 viastyle="Through Hole" minholewidth=10 minwidth=20 maxholewidth=10 maxwidth=30
ShortCircuit [All] p0: scope1count=1 scope1_0_kind=Board scope1_0_value=Board scope2count=1 scope2_0_kind=Board scope2_0_value=Board commentlength=0 allowed=FALSE
SilkToBoardRegionClearance [All] p0 off: scope1count=1 scope1_0_kind=Board scope1_0_value=Board scope2count=1 scope2_0_kind=Board scope2_0_value=Board commentlength=130 // Protel DXP Scope 1 Expression Was: Not ((IsComment or IsDesignator) And (Hide <> 'False')) and not InRegion(1000,500,4000,800)
SilkToBoardRegionClearance [Not ((IsComment or IsDesignator) And (Hide <> 'False')) and not InRegion(1000,500,4000,800)] p1:
SilkToSilkClearance [All] p0: scope1count=1 scope1_0_kind=Board scope1_0_value=Board scope2count=1 scope2_0_kind=Board scope2_0_value=Board commentlength=0
SilkToSilkClearance SilkToSilkClearance_Pb-FreeLogo [All] p0 off: scope1count=1 scope1_0_kind=Board scope1_0_value=Board scope2count=1 scope2_0_kind=Board scope2_0_value=Board commentlength=120 // Protel DXP Scope 2 Expression Was: (HasFootprint('Pb-Free_Overlay_Medium') OR HasFootprint('Pb-Free_Overlay_Small'))
SilkToSilkClearance SilkToSilkClearance_Pb-FreeLogo [(HasFootprint('Pb-Free_Overlay_Medium') OR HasFootprint('Pb-Free_Overlay_Small')) vs (HasFootprint('Pb-Free_Overlay_Medium') OR HasFootprint('Pb-Free_Overlay_Small'))] p1: silktosilkclearance=1
SilkToSilkClearance [All] p2: silktosilkclearance=1
SilkToSolderMaskClearance [All] p0 off: scope1count=1 scope1_0_kind=Board scope1_0_value=Board scope2count=1 scope2_0_kind=Board scope2_0_value=Board commentlength=44 // Protel DXP Scope 1 Expression Was: IsPad
SilkToSolderMaskClearance [IsPad] p1: minsilkscreentomaskgap=1 clearancetoexposedcopper=TRUE
SolderMaskExpansion [All] p0: scope1count=1 scope1_0_kind=Board scope1_0_value=Board scope2count=1 scope2_0_kind=Board scope2_0_value=Board commentlength=0 expansion=1.97
SolderMaskExpansion [All] p1: expansion=1.97 istentingtop=FALSE
UnRoutedNet [All] p0: scope1count=1 scope1_0_kind=Board scope1_0_value=Board scope2count=1 scope2_0_kind=Board scope2_0_value=Board commentlength=0
UnRoutedNet [All] p1: checkbadconnections=TRUE
UnpouredPolygon [All] p0: scope1count=1 scope1_0_kind=Board scope1_0_value=Board scope2count=1 scope2_0_kind=Board scope2_0_value=Board commentlength=0
Width [All] p0: scope1count=1 scope1_0_kind=Board scope1_0_value=Board scope2count=1 scope2_0_kind=Board scope2_0_value=Board commentlength=0 maxlimit=100 minlimit=6 preferedwidth=10
Width [All] p1: maxlimit=100 minlimit=6 preferedwidth=10 checkconnectedcopper=TRUE
13 further rules are at their usual default settings.

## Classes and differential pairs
component class Screw: H13 H14 H15 H16
net class High_Voltage: OUTA OUTC VM
component class DRV7308EVM_rev1_POWER_AND_CONNECTORS_SLF: C4 C13 C14 C15 C17 C24 C25 C26 C27 C34 C35 C37 C38 C39 C40 C41 C42 C43 C44 C45 C46 C47 C48 C49 C50 C56 C57 C58 C62 C63 C64 D7 D9 D10 D11 D12 F1 F2 HALL_PWR J1 J2 J5 J6 J7 J8 J9 J10 J18 J19 L2 L3 L4 NT1 NT2 NT13 NT14 R14 R22 R29 R30 R31 R43 R44 R46 R47 R52 R53 R55 R56 R57 R58 R59 R60 R61 R62 R63 R64 R65 R66 R67 R68 R69 R70 R71 R72 R73 R74 R78 R79 R91 R92 R93 R94 R98 R99 R100 R101 R102 R103 R104 R105 R106 R107 R108 R109 R110 R111 R112 R113 R116 R118 R119 R121 R122 R130 R134 RT1 RV1 SH-J1 SH-J3 SH-J4 SH-J5 TP11 TP12 TP13 TP14 TP16 TP17 TP31 TP42 TP50 TP52 TP53 TP54 TP55 TP56 TP57 U3 U5
component class Shunt: SH-J1 SH-J2 SH-J3 SH-J4 SH-J5
component class DRV7308EVM_rev1_DRIVER_SLF: 40 C1 C2 C3 C5 C6 C7 C8 C9 C10 C11 C12 C16 C18 C19 C20 C21 C22 C23 C28 C29 C30 C31 C32 C33 C36 C52 C53 C54 C55 C59 C60 C61 C67 D2 D3 D4 D14 D15 D16 D? J3 J4 J17 L1 NT3 NT4 NT5 NT6 NT7 NT8 NT9 NT10 NT11 NT12 R1 R2 R3 R4 R5 R6 R7 R8 R9 R10 R11 R12 R13 R15 R16 R17 R18 R19 R20 R21 R34 R36 R37 R41 R45 R48 R49 R50 R51 R54 R75 R76 R77 R117 R120 R123 R124 R125 R126 R127 R128 R129 R135 R137 R138 R139 SH-J2 TP1 TP2 TP3 TP4 TP5 TP6 TP7 TP8 TP9 TP10 TP18 TP19 TP20 TP21 TP22 TP23 TP24 TP26 TP29 TP30 TP32 TP33 TP34 TP35 TP36 TP37 TP38 TP39 TP40 TP41 TP43 TP44 TP45 TP46 TP47 TP48 TP49 U1 U2 U4
component class Header: J1 J2 J8 J17 J18
component class Logo: Logo2
component class DRV7308EVM_rev1_HARDWARE_SLF: FID1 FID2 FID3 H9 H10 H11 H12 H13 H14 H15 H16 LOGO Logo1 Logo2 Logo3 Logo4 LOGO5 LOGO6 LOGO7 LOGO8 MH5 MH6 MH7 MH8 ZZ1 ZZ2 ZZ3 ZZ4
component class FiducialMark: FID1 FID2 FID3
component class AssemblyNote: ZZ1 ZZ2 ZZ3 ZZ4

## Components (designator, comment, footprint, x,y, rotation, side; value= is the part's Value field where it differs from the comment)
C1 "12063C105KAT2A" 1206L 3694,3451 r90 top
C2 "CL05B104KP5NNNC" 0402L 2318,753.76 r270 top
C3 "12063C105KAT2A" 1206L 4079,3566 r0 top
C4 "C0805C471K5RACTU" 0805L 4256,1131 r0 top
C5 "12063C105KAT2A" 1206L 4357,3476 r90 top
C6 "VJ2225Y104KXGAT" FP-VJ2225Y104KXGAT_2225-IPC_A 3143,3069 r90 top
C7 "885012206095" 0603L 2147,858.44 r180 top
C8 "VJ2225Y104KXGAT" FP-VJ2225Y104KXGAT_2225-IPC_A 3424,3068.81 r90 top
C9 "08053C104KAT2A" 0805_HV 3678,3024 r0 top
C10 "GRM32ER71E226KE15L" 1210_270L 3613,2867 r0 top
C11 "CL05B103KA5NNNC" 0402L 3804,2775 r180 top
C12 "885012206003" WCAP-CSGP_0603_L1.6W0.8H0.8_Reflow 4374,2755 r270 top
C13 "885012206069" FP-885012206069_0603-MFG 5089,961.53 r270 top
C14 "885012206069" FP-885012206069_0603-MFG 5376,962.53 r270 top
C15 "885012206069" FP-885012206069_0603-MFG 5186,963.53 r270 top
C16 "885012206003" WCAP-CSGP_0603_L1.6W0.8H0.8_Reflow 3749,2658 r90 top
C17 "885012206003" WCAP-CSGP_0603_L1.6W0.8H0.8_Reflow 4134,1555 r0 top
C18 "885012206083" 0603L 4802.59,2608.59 r0 top
C19 "885012206083" 0603L 5001.36,2605.29 r0 top
C20 "885012206083" 0603L 5203.36,2606.29 r0 top
C21 "885012206083" 0603L 5410.59,2611.59 r0 top
C22 "885012206083" 0603L 5610.59,2609.59 r0 top
C23 "885012206083" 0603L 5757.61,2616.59 r180 top
C24 "885012206003" WCAP-CSGP_0603_L1.6W0.8H0.8_Reflow 3749,1641 r270 top
C25 "885012206034" 0603L 5542.82,2147 r0 top
C26 "885012206034" 0603L 5640.82,2147 r0 top
C27 "885012206034" 0603L 5202.82,527 r180 top
C28 "LMK107B7105KAHT" 0603L 2303,1601.44 r0 top
C29 "CGA3E1X7R1E105K080AC" 0603L 2143,1017.44 r180 top
C30 "CGA3E1X7R1E105K080AC" 0603L 2143,964.44 r180 top
C31 "CGA3E1X7R1E105K080AC" 0603L 2144,911.44 r180 top
C32 "C3216X7R1E106K160AB" 1206_180L 2342,1047.44 r0 top
C33 "EMK107B7104KA-T" 0603L 2303,1548.44 r0 top
C34 "885012206069" FP-885012206069_0603-MFG 5280,961.53 r270 top
C35 "885012206095" 0603L 3431,1599 r270 top
C36 "885012206003" WCAP-CSGP_0603_L1.6W0.8H0.8_Reflow 4385,2568 r270 top
C37 "885012206003" WCAP-CSGP_0603_L1.6W0.8H0.8_Reflow 4234,1796.53 r270 top
C38 "C1005X5R1A225K050BC" 0402L 3960.26,1365.14 r0 top
C39 "885012206034" 0603L 4142.56,1770 r180 top
C40 "885012206003" WCAP-CSGP_0603_L1.6W0.8H0.8_Wave 4048.26,1795.14 r90 top
C41 "885012206003" WCAP-CSGP_0603_L1.6W0.8H0.8_Reflow 3800,1798 r270 top
C42 "885012206034" 0603L 3894.26,1771.14 r0 top
C43 "885012206003" WCAP-CSGP_0603_L1.6W0.8H0.8_Reflow 3985,1798 r90 top
C44 "885012206003" WCAP-CSGP_0603_L1.6W0.8H0.8_Reflow 4479,1799.53 r270 top
C45 "885012206034" 0603L 4376.56,1775 r180 top
C46 "885012206003" WCAP-CSGP_0603_L1.6W0.8H0.8_Reflow 4296,1799.53 r90 top
C47 "C0805C471K5RACTU" 0805L 5512.82,927 r0 top
C48 "C0805C471K5RACTU" 0805L 5630.82,927 r180 top
C49 "C0805C471K5RACTU" 0805L 5744.82,925 r0 top
C50 "885012206003" WCAP-CSGP_0603_L1.6W0.8H0.8_Reflow 4520,1644 r270 top
C52 "885012206095" 0603L 4354,2487 r180 top
C53 "06031C103JAT2A" 0603L 5462.14,521.69 r0 top
C54 "C3216X7R1E106K160AB" 1206_180L 2342,1137.44 r0 top
C55 "LMK107B7105KAHT" 0603L 2308,1337.9 r0 top
C56 "B32922C3334M" B32922_14.5mm 1755,4339.36 r0 top
C57 "381LQ151M450J022" 381LQ_J02 2450.24,3066.15 r270 top
C58 "381LQ151M450J022" 381LQ_J02 1372,3069 r270 top
C59 "UBT1E221MPD1TD" BT_1000x1250 3522.57,3603 r180 top
C60 "UBT1E221MPD1TD" BT_1000x1250 4078,3693 r180 top
C61 "UBT1E221MPD1TD" BT_1000x1250 4524,3600 r0 top
C62 "GR442QR73D102KW01L" 1808 3654,5332.32 r90 bottom
C63 "GR442QR73D102KW01L" 1808 4040.9,5329 r90 bottom
C64 "GR442QR73D102KW01L" 1808 4468,5332.32 r90 bottom
C67 "EKMG250ELL102MJ20S" Chemi-Con_1000x2000 3475,2577 r180 top
D2 "LTST-C170KRKT" LED_LTST-C170_Red 4780,3035.42 r270 top
D3 "GVDD_LED" LTST-C170KGKT_Green 1459,1605.34 r270 top
D4 "MCU_LED" LTST-C170KFKT_Orange 5978.28,2520.42 r90 top
D7 "GBU606" GBU 1734,4842 r0 top
D9 "MMDL101T1G" SOD-323 5412.82,846 r90 top
D10 "MMDL101T1G" SOD-323 5325.82,843 r90 top
D11 "MMDL101T1G" SOD-323 5230.82,845.31 r90 top
D12 "MMDL101T1G" SOD-323 5132.82,847 r90 top
D14 "MMSZ5248BS-7-F" SOD-323 3570.69,3884 r180 top
D15 "MMSZ5248BS-7-F" SOD-323 4472.31,3879 r0 top
D16 "MMSZ5248BS-7-F" SOD-323 4181.69,3964 r180 top
F1 "0443003.DR" FUSE_0443 1056,5337 r90 top
F2 "0443003.DR" FUSE_0443 1215,3849 r270 top
FID1 "Fiducial" Fiducial10-20#1 864,5092 r0 top
FID2 "Fiducial" Fiducial10-20#2 5553.69,5216.5 r0 top
FID3 "Fiducial" Fiducial10-20#1 5966.33,355.55 r0 top
H9 "24438" Keystone24438 6496,5836 r180 bottom
H10 "24438" Keystone24438 6496,164 r180 bottom
H11 "24438" Keystone24438 637,164 r180 bottom
H12 "24438" Keystone24438 637,5836 r180 bottom
H13 "MPMS 003 0005 PH" BuildingFastener_MPMS_003_0005_PH 6496,5836 r0 top
H14 "MPMS 003 0005 PH" BuildingFastener_MPMS_003_0005_PH 6496,164 r0 top
H15 "MPMS 003 0005 PH" BuildingFastener_MPMS_003_0005_PH 637,164 r0 top
H16 "MPMS 003 0005 PH" BuildingFastener_MPMS_003_0005_PH 637,5836 r0 top
J1 "SLEW_SEL" TSW-104-07-G-D 3073.23,1728 r270 top
J2 "HALL_PWR_SEL" FCI_68001-403HLF 5797,5404 r180 top
J3 "SSQ-110-03-G-D" Samtec_SSQ-110-03-x-D 5379.82,653 r0 bottom
J4 "SSQ-110-03-G-D" Samtec_SSQ-110-03-x-D 5379.82,2353 r0 bottom
J5 "CT3151SP-2" CTE_CT3151SP-2 -171,3227 r0 top
J6 "1904150" Phoenix_1904150 4064,5245 r180 top
J7 "HALL IN" Phoenix_1792892 5711.74,5771 r180 top
J8 "CSA_OFFSET_SEL" WURTH_61300311121 3995.7,1168 r180 top
J9 "GVDD" On-Shore_OSTVN02A150 1196,2248 r90 top
J10 "CT3151SP-0" CTE_CT3151SP-0 -190,2494 r0 top
J17 "BK_PWR" TSW-102-07-G-S 2113,1126.44 r0 top
J18 "ILIM_PWR_SEL" FCI_68001-403HLF 3573,1855 r0 top
J19 "Power input" Phoenix_1904150 1787.5,5659 r180 top
L1 "78438335047" WE-MAIA_3015 2275,916.44 r90 top
L2 "742792511" 1812_170_HighSpeed 3531,4410 r90 top
L3 "742792511" 1812_170_HighSpeed 4055,4406 r90 top
L4 "742792511" 1812_170_HighSpeed 4583,4408 r90 top
LOGO "CAUTION HOT SURFACE" IEC_HotSurface_Small 5276,3541 r0 top
Logo1 "CE Mark" CE_Mark_5mm 3517,810 r0 top
Logo2 "Texas Instruments" TI_Stacked_Overlay_Small 1256,509 r0 top
Logo3 "FCC disclaimer" FCC_disclaimer 4890,4499.8 r90 top
Logo4 "WEEE logo" WEEE_Minimum 3100,820.64 r0 top
LOGO5 "CAUTION HOT SURFACE" IEC_HotSurface_Small 3169,3886 r0 top
LOGO6 "DANGER HIGH VOLTAGE" IEC_HighVoltage_Small 4058,4722 r0 top
LOGO7 "CAUTION HOT SURFACE" IEC_HotSurface_Small 3817,2269 r0 top
LOGO8 "DANGER HIGH VOLTAGE" IEC_HighVoltage_Small 2463.51,4800.51 r0 top
MH5 "MTG_Pads" MTGP_M3_PanHead 6496,5836 r0 top
MH6 "MTG_Pads" MTGP_M3_PanHead 6496,164 r0 top
MH7 "MTG_Pads" MTGP_M3_PanHead 637,164 r0 top
MH8 "MTG_Pads" MTGP_M3_PanHead 637,5836 r0 top
NT1 "Net-Tie" Net-Tie_50milWide_30milLong 854,2263.85 r180 top net-tie
NT2 "Net-Tie" Net-Tie_50milWide_30milLong 858,2101 r180 top net-tie
NT3 "Net-Tie" Net-Tie_10mil 4070,2762 r0 top net-tie
NT4 "Net-Tie" Net-Tie_10mil 4073,2745 r0 top net-tie
NT5 "Net-Tie" Net-Tie_10mil 3954,2762 r0 top net-tie
NT6 "Net-Tie" Net-Tie_10mil 3954,2743 r0 top net-tie
NT7 "Net-Tie" Net-Tie_10mil 4186,2762 r0 top net-tie
NT8 "Net-Tie" Net-Tie_10mil 4186,2744 r0 top net-tie
NT9 "Net-Tie" Net-Tie_10milWide_30milLong#1 3740,3292 r180 top net-tie
NT10 "Net-Tie" Net-Tie_10milWide_30milLong#1 3915,3573 r180 top net-tie
NT11 "Net-Tie" Net-Tie_10milWide_30milLong#1 4334,3284 r0 top net-tie
NT12 "Net-Tie" Net-Tie_10milWide_30milLong#1 3291,3338 r270 top net-tie
NT13 "Net-Tie" Net-Tie_10milWide_30milLong#2 3633,2844 r90 top net-tie
NT14 "Net-Tie" Net-Tie_50milWide_30milLong 859,1956 r180 top net-tie
R1 "CRCW0603162KFKEA" 0603L 2186,1237.44 r0 top
R2 "ERJ-3GEY0R00V" 0603L 5329.93,504.56 r90 top
R3 "CSR1206FK30L0" 1206L 3925,2753 r90 top
R4 "RT0603DRE0722K1L" 0603L 2080,1236.44 r0 top
R5 "ERJ-6GEY0R00V" 0805L 3975,2869 r180 top
R6 "CSR1206FK30L0" 1206L 4038.82,2753 r90 top
R7 "ERJ-6GEY0R00V" 0805L 2288,1234.44 r90 top
R8 "CRCW040220K0FKED" 0402L 4288,2565 r90 top
R9 "CRCW040210R2FKED" 0402L 4356.68,2681 r0 top
R10 "ERJ-2RKF2001X" 0402L 3823,2831 r90 top
R11 "CRCW040210R2FKED" 0402L 4359,2642 r0 top
R12 "ERJ-2RKF2001X" 0402L 3784,2832 r90 top
R13 "ERJ-6GEY0R00V" 0805L 4927.82,468.6 r90 top
R14 "CRCW0805330RFKEAC" 0805L 4241,1204 r180 top
R15 "ERA3AEB331V" 0603L 4695,3021.42 r270 top
R16 "RT0603BRD074K7L" 0603L 1383,1589.44 r270 top
R17 "ERA3AEB331V" 0603L 5857.19,2535.03 r90 top
R18 "RC0603FR-07100RL" 0603L 4802.59,2555.59 r180 top
R19 "RC0603FR-07100RL" 0603L 5000.59,2552.59 r180 top
R20 "RC0603FR-07100RL" 0603L 5201.59,2553.59 r180 top
R21 "ERJ-6GEY0R00V" 0805L 4096.13,2870 r180 top
R22 "RC1206FR-07330KL" 1206 1742,4096 r180 top
R29 "TNPW060310K0BEEA" TNPW0603 5540.82,2215 r0 top
R30 "TNPW060310K0BEEA" TNPW0603 5637.82,2215 r180 top
R31 "TNPW060310K0BEEA" TNPW0603 5200.82,457 r180 top
R34 "CRCW06035K10JNEA" 0603L 2904,1926 r270 top
R36 "ERJ-6GEY0R00V" 0805L 4900.82,805 r180 top
R37 "CSR1206FK30L0" 1206L 4154,2753 r90 top
R41 "CRCW06035K10JNEA" 0603L 4582,3078 r90 top
R43 "CRCW060310K0JNEA" 0603L 2913.23,1705 r270 top
R44 "CRCW060368K0FKEA" FP-CRCW060368K0FKEA_0603-MFG 2914.23,1609 r270 top
R45 "CRCW040220K0FKED" 0402L 3862,2831 r270 top
R46 "CRCW060349K9FKEA" 0603L 4225,1641 r270 top
R47 "CRCW06030000Z0EA" 0603L 3953.26,1532.14 r90 top
R48 "ERJ-3GEY0R00V" 0603L 5630.82,495.56 r90 top
R49 "ERJ-3GEY0R00V" 0603L 5730.82,493 r90 top
R50 "ERJ-3GEY0R00V" 0603L 5830.82,494 r90 top
R51 "ERJ-3GEY0R00V" 0603L 5834.82,2186 r90 top
R52 "CRCW060310R2FKEA" 0603L 4169.56,1846 r270 top
R53 "CRCW06034K99FKEA" 0603L 4172.56,1695 r270 top
R54 "ERJ-3GEY0R00V" 0603L 2301,1654.44 r0 top
R55 "CRCW060310R2FKEA" 0603L 4113.56,1848 r270 top
R56 "CRCW06034K99FKEA" 0603L 4113.56,1695 r270 top
R57 "CRCW060349K9FKEA" 0603L 4060.56,1693 r90 top
R58 "CRCW060349K9FKEA" 0603L 3814.26,1639.14 r270 top
R59 "CRCW060310R2FKEA" 0603L 3865.26,1846.14 r270 top
R60 "CRCW06034K99FKEA" 0603L 3867.26,1695.14 r270 top
R61 "CRCW060310R2FKEA" 0603L 3920.26,1846.14 r270 top
R62 "CRCW06034K99FKEA" 0603L 3920.26,1695.14 r270 top
R63 "CRCW060349K9FKEA" 0603L 3973.26,1695.14 r90 top
R64 "CRCW060349K9FKEA" 0603L 4455,1643 r270 top
R65 "CRCW060310R2FKEA" 0603L 4414,1854 r270 top
R66 "CRCW06034K99FKEA" 0603L 4402.56,1699 r270 top
R67 "CRCW060310R2FKEA" 0603L 4361,1853.56 r270 top
R68 "CRCW06034K99FKEA" 0603L 4348.56,1699 r270 top
R69 "CRCW060349K9FKEA" 0603L 4295.56,1699 r90 top
R70 "CRCW0805330RFKEAC" 0805L 5483.82,1015 r90 top
R71 "CRCW0805330RFKEAC" 0805L 5656.82,1021 r90 top
R72 "CRCW0805330RFKEAC" 0805L 5730.82,1020 r90 top
R73 "CRCW0603100KFKEA" 0603L 4273.26,1543.14 r90 top
R74 "CRCW0603100KFKEA" 0603L 4326.26,1542.14 r270 top
R75 "RC0603FR-07100RL" 0603L 5410.59,2558.59 r180 top
R76 "RC0603FR-07100RL" 0603L 5610.59,2556.59 r180 top
R77 "RC0603FR-07100RL" 0603L 5759.56,2564 r0 top
R78 "ERJ-3GEY0R00V" 0603L 5458.82,1129 r90 top
R79 "ERJ-3GEY0R00V" 0603L 5511.82,1128 r90 top
R91 "RC1206FR-07332KL" 1206 3047,4453 r270 top
R92 "RC1206FR-07332KL" 1206 5023.3,4936 r90 top
R93 "RC1206FR-07332KL" 1206 5474,4939 r90 top
R94 "RC1206FR-07332KL" 1206 5932,4941 r90 top
R98 "RC1206FR-07332KL" 1206 3048,4673.54 r270 top
R99 "RC0603FR-078K2L" 0603 5004,5710 r180 top
R100 "RC0603FR-078K2L" 0603 5004.44,5634 r180 top
R101 "RC0603FR-078K2L" 0603 5074,4310 r90 top
R102 "RC0603FR-078K2L" 0603 4995,4311.53 r90 top
R103 "RC0603FR-078K2L" 0603 5450.27,4311.54 r90 top
R104 "RC0603FR-078K2L" 0603 5553.69,4311.54 r90 top
R105 "RC0603FR-078K2L" 0603 5981,4313 r90 top
R106 "RC0603FR-078K2L" 0603 5881,4312 r90 top
R107 "CRCW080520K0FKEA" 0805L 5512.82,854 r180 top
R108 "CRCW080520K0FKEA" 0805L 5629.93,854 r0 top
R109 "CRCW080520K0FKEA" 0805L 5745.82,852 r180 top
R110 "RC1206FR-07332KL" 1206 5023.3,4709.83 r90 top
R111 "RC1206FR-07332KL" 1206 5473,4713.88 r90 top
R112 "RC1206FR-07332KL" 1206 5931,4713 r90 top
R113 "RC1206FR-07332KL" 1206 3048,4895 r270 top
R116 "RC1206FR-07332KL" 1206 5023,4489.53 r90 top
R117 "CRCW06035K10JNEA" 0603L 4891.82,258.56 r90 top
R118 "CRCW060349K9FKEA" 0603L 3378,1701.44 r90 top
R119 "CRCW06032K67FKEA" 0603L 3378,1598.44 r90 top
R120 "RC0603FR-07100RL" 0603L 5435.7,444.13 r90 top
R121 "RC1206FR-07330KL" 1206 1529,4096 r180 top
R122 "RC1206FR-07330KL" 1206 1954.41,4095 r180 top
R123 "CRCW06035K10JNEA" 0603L 5146.82,253 r90 top
R124 "CRCW06035K10JNEA" 0603L 5015,2992 r270 top
R125 "CRCW06035K10JNEA" 0603L 5068,2992 r270 top
R126 "CRCW06035K10JNEA" 0603L 5124,2992.44 r270 top
R127 "CRCW06035K10JNEA" 0603L 4522,3076.38 r270 top
R128 "CRCW040220K0FKED" 0402L 3861,2905 r180 top
R129 "ERJ-2RKF2001X" 0402L 4327,2564 r270 top
R130 "RC1206FR-07332KL" 1206 5475,4485 r90 top
R134 "RC1206FR-07332KL" 1206 5932,4489 r90 top
R135 "ERJ-3GEY0R00V" 0603L 5051.7,494.69 r90 top
R137 "ERJ-3GEY0R00V" 0603L 5382.7,493.13 r90 top
R138 "ERJ-3GEY0R00V" 0603L 5721.64,2198.03 r90 top
R139 "ERJ-3GEY0R00V" 0603L 5562.7,2498.69 r180 top
RT1 "CL-40" Thermistor_CL-40 1013,4507 r270 top
RV1 "B72210P2351K101" FP-B72210P2351K101_RADIAL-MFG 1705,5182 r180 top
SH-J1 "SNT-100-BK-G" SNT-100-BK-G 4042.77,1171.44 r180 top
SH-J2 "SNT-100-BK-G" SNT-100-BK-G 2117,1129 r180 top
SH-J3 "SNT-100-BK-G" SNT-100-BK-G 5746,5404 r180 top
SH-J4 "SNT-100-BK-G" SNT-100-BK-G 3073,1877 r180 top
SH-J5 "SNT-100-BK-G" SNT-100-BK-G 3521,1848 r180 top
TP1 "OUTA" Keystone5000 3512,4086 r90 top
TP2 "OUTB" Keystone5000 4051,4087.68 r90 top
TP3 "OUTC" Keystone5000 4592,4087 r90 top
TP4 "K_OUTA" Keystone5000 3342.08,4213.18 r90 top
TP5 "K_LS_D" Keystone5000 3364.77,4340.4 r90 top
TP6 "K_OUTB" Keystone5000 3894.61,4348.54 r180 top
TP7 "K_OUTB" Keystone5000 3816.29,4245.27 r180 top
TP8 "INHA" Testpoint_Keystone_Miniature 4773.59,2701.59 r0 top
TP9 "K_OUTC" Keystone5000 4838.99,3661.43 r90 top
TP10 "K_LS_D" Keystone5000 4821.5,3468 r90 top
TP11 "GND" Harwin_D3082-05 2900,433 r180 top
TP12 "PGND" Harwin_D3082-05 754,1956 r270 top
TP13 "PGND" Harwin_D3082-05 569,1965 r270 top
TP14 "SNB" Keystone5002 4169.19,2134 r270 top
TP16 "GND" Keystone5001 6227,286 r90 top
TP17 "PGND" Keystone5001 4005.73,2444 r90 top
TP18 "INHB" Testpoint_Keystone_Miniature 5177.59,2698.59 r0 top
TP19 "LDO_IN" Keystone5009 2168,1360 r90 top
TP20 "INLB" Testpoint_Keystone_Miniature 5383.59,2699.59 r180 top
TP21 "INLA" Testpoint_Keystone_Miniature 4974.59,2697.59 r180 top
TP22 "INHC" Testpoint_Keystone_Miniature 5584.59,2699.59 r180 top
TP23 "INLC" Testpoint_Keystone_Miniature 5785.59,2702.59 r0 top
TP24 "SLEW" Testpoint_Keystone_Miniature 3126,1424 r180 top
TP26 "3.3V" Keystone5002 2539,1614.52 r90 top
TP29 "BOOTA" Keystone5000 3684,4449 r90 top
TP30 "+5V" Keystone5009 4753.82,739 r180 top
TP31 "SNA" Keystone5002 3812.26,1973.14 r270 top
TP32 "BOOTB" Keystone5000 4208,4357 r90 top
TP33 "BK_PWR" Keystone5009 1920,1213 r0 top
TP34 "BOOTC" Keystone5000 4435,4293 r90 top
TP35 "VM" Keystone5000 887,3479 r90 top
TP36 "ILIMIT" Keystone5002 3537,1654 r90 top
TP37 "AMPIN+" Keystone5002 4636.51,2445.01 r90 top
TP38 "AMPIN-" Keystone5002 4636,2285 r90 top
TP39 "AMPOUT" Keystone5002 3659,1561 r180 top
TP40 "K_VM" Keystone5000 2880,3707 r90 top
TP41 "K_VM" Keystone5000 2656,3703 r90 top
TP42 "GVDD" Keystone5009 1661,1979 r0 top
TP43 "ENABLE" Testpoint_Keystone_Miniature 2850,1325 r180 top
TP44 "BRAKE" Keystone5002 5339.09,3012.11 r90 top
TP45 "nFAULT" Testpoint_Keystone_Miniature 4893,3048 r90 top
TP46 "VTEMP" Keystone5002 4742.82,388 r90 top
TP47 "SLA" Keystone5002 3973.26,1965.14 r90 top
TP48 "SLB" Keystone5002 4083.96,2037.14 r90 top
TP49 "SLC" Keystone5002 4251.26,2033.14 r270 top
TP50 "K_GVDD" Keystone5009 3263,2037 r0 top
TP52 "HALL_EXT" Keystone5002 6069,5406 r90 top
TP53 "HALL_PWR" Keystone5002 6072,5259 r90 top
TP54 "SNC" Keystone5002 4421.26,2036.14 r90 top
TP55 "ISENA" Keystone5002 5534.82,1330 r180 top
TP56 "ISENB" Keystone5002 5663.82,1328 r180 top
TP57 "ISENC" Keystone5002 5792.82,1322 r180 top
U1 "DRV7308HRENR" REN0065A-MFG 4037.07,3196.38 r90 top
U2 "TLV74133PDBVR" DBV0005A_N 2314,1442.9 r90 top
U3 "TPD4S009DCKR" DCK0006A_N 5153.09,1263.38 r0 top
U4 "LMR51420YFDDCR" DDC0006A-MFG 2218.7,753.67 r270 top
U5 "TLV9064IPWR" PW0014A_N 4150.26,1362.14 r0 top
ZZ1 "This Assembly Note is for PCB labels only" AssemblyNoteLabel 213.77,7380.7 r0 top
ZZ2 "These assemblies are ESD sensitive, ESD precautions shall be observed." AssemblyNote 213.77,7271.82 r0 top
ZZ3 "These assemblies must be clean and free from flux and all contaminants. Use of no clean flux is not acceptable." AssemblyNote 213.77,7183.26 r0 top
ZZ4 "These assemblies must comply with workmanship standards IPC-A-610 Class 2, unless otherwise specified." AssemblyNote 213.77,7094.7 r0 top

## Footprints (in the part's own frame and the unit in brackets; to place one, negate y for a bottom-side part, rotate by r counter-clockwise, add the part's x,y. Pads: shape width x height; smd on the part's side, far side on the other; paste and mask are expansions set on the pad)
381LQ_J02 [mm] "TH, 2-Leads, Dia 25mm, Pin Spacing 10mm"
  rrect50% 3x3 hole 2: 1(-5,0)
  round 3 hole 2: 2(5,0)
0402L [mm] "0402 from SM-752 data"
  rect 0.6x0.5 smd: 1(-0.5,0) 2(0.5,0)
0603 [mm] "0603 from SM-752 data"
  rect 1x0.95 smd: 1(-0.8,0) 2(0.8,0)
  silkscreen extent -1.52,-0.69 1.52,0.69
0603L [mm] "0603 from SM-752 data"
  rect 0.8x0.85 smd: 1(-0.7,0) 2(0.7,0)
  silkscreen extent -0.07,-0.33 0.07,0.33
0805_HV [mil] "0805 with 30mil clearance between pads"
  rect 50x63 smd: 1(-40,0) 2(40,0)
  silkscreen extent -74,-40 74,40
0805L [mm] "0805 from SM-752 data"
  rect 1.1x1.4 smd: 1(-0.75,0) 2(0.75,0)
1206 [mm] "1206 from SM-752 data"
  rect 1.3x1.85 smd: 1(-1.45,0) 2(1.45,0)
  silkscreen extent -2.4,-1.21 2.4,1.21
1206_180L [mm] "1206_180"
  rect 1.1x1.75 smd: 1(-1.35,0) 2(1.35,0)
  silkscreen extent -0.4,-0.77 0.4,0.77
1206L [mm] "1206 from SM-752 data"
  rect 1.1x1.75 smd: 1(-1.35,0) 2(1.35,0)
  silkscreen extent -0.4,-0.77 0.4,0.77
1210_270L [mm] "1210"
  rect 1.1x2.6 smd: 1(-1.35,0) 2(1.35,0)
  silkscreen extent -0.4,-1.2 0.4,1.2
1808 [mm] "Chip Capacitor, Body 4.6x2.0mm, IPC Medium Density"
  rect 1.4x2.3 smd: 1(-2.1,0) 2(2.1,0)
  silkscreen extent -3.1,-1.45 3.1,1.45
1812_170_HighSpeed [mm] "Wurth recommended land pattern"
  rrect7% 1.4x3 smd: 1(-2.45,0) 2(2.45,0)
  silkscreen extent -1.5,-1.5 1.5,1.5
AssemblyNote [mil] "Assembly Note"
AssemblyNoteLabel [mil] "Assembly Note for PCB Labels"
B32922_14.5mm [mm] "Epcos film capacitors, 15mm spacing"
  rect 1.5x1.5 hole 1: 1(-7.5,0)
  round 1.5 hole 1: 2(7.5,0)
  silkscreen extent -9,-4.25 9,4.25
BT_1000x1250 [mm] "Nichicon"
  rect 1.35x1.35 hole 0.85 paste+0: 1(-2.5,0)
  round 1.35 hole 0.85 paste+0: 2(2.5,0)
  silkscreen extent -5.58,-5.4 5.4,5.4
BuildingFastener_MPMS_003_0005_PH [mil] "MACHINE SCREW PAN PHILLIPS M3"
  round 1 on Mech3: 0(0,0)
CE_Mark_5mm [mil] "Minimum text height for CE Mark"
Chemi-Con_1000x2000 [mm] "TH, 2-Leads, Body 10x20mm, Pin Spacing 5mm"
  rect 1.35x1.35 hole 0.85: 1(-2.5,0)
  round 1.35 hole 0.85: 2(2.5,0)
  silkscreen extent -5.25,-5.25 5.25,5.25
CTE_CT3151SP-0 [mm] "Banana Jack Insul Nylon Black, R/A, TH"
  round 2.1 hole 1.6: 1(18.898,-2.54) 1(18.898,2.54) 1(23.978,-2.54) 1(23.978,2.54)
  silkscreen extent 0.44,-6.75 18.02,6.75
CTE_CT3151SP-2 [mm] "Banana Jack Insul Nylon Red, R/A, TH"
  round 2.1 hole 1.6: 1(18.898,-2.54) 1(18.898,2.54) 1(23.978,-2.54) 1(23.978,2.54)
  silkscreen extent 0.44,-6.75 18.02,6.75
DBV0005A_N [mm] "SOT23, 5-Leads, Body 2.9x1.6mm, Pitch 0.95mm, Lead Span 2.8mm, IPC Medium Density"
  rrect17% 1x0.6 smd: 1(-1.375,0.95) 2(-1.375,0) 3(-1.375,-0.95) 4(1.375,-0.95) 5(1.375,0.95)
  silkscreen extent -0.25,-1.55 0.25,1.55
DCK0006A_N [mm] "SOT23, 6-Leads, Body 2x1.3mm, Pitch 0.65mm, Lead Span 2.1mm, IPC Medium Density"
  rrect25% 0.85x0.4 smd: 1(-1.125,0.65) 2(-1.125,0) 3(-1.125,-0.65) 4(1.125,-0.65) 5(1.125,0) 6(1.125,0.65)
  silkscreen extent -1.5,-1.09 0.51,1.09
DDC0006A-MFG [mm]
  rrect17% 1.1x0.6 smd paste+0 mask+0: 1(-1.35,0.95) 2(-1.35,0) 3(-1.35,-0.95) 4(1.35,-0.95) 5(1.35,0) 6(1.35,0.95)
  silkscreen extent -2.57,-1.53 0.42,1.53
FCC_disclaimer [mil]
FCI_68001-403HLF [mm] "Header, 2.54mm, 3x1, TH"
  rect 1.55x1.55 hole 1.02: 1(-2.54,0)
  round 1.55 hole 1.02: 2(0,0) 3(2.54,0)
  silkscreen extent -3.81,-1.21 3.81,1.5
Fiducial10-20#1 [mm]
  round 1 smd mask+0: 1(0,0)
  Top Layer keep-out circle w1.178: c0,0 r0.5
Fiducial10-20#2 [mm]
  round 1 smd mask+0.5: 1(0,0)
  Top Layer keep-out circle w1.178: c0,0 r0.5
FP-885012206069_0603-MFG [mm]
  rrect13% 0.8x0.8 smd paste+0 mask+0: 1(-0.75,0) 2(0.75,0)
FP-B72210P2351K101_RADIAL-MFG [mm]
  rrect6% 1.55x1.55 hole 1 paste-1000 mask+0: 1(-3.75,1.95)
  round 1.55 hole 1 paste-1000 mask+0: 2(3.75,-1.95)
FP-CRCW060368K0FKEA_0603-MFG [mm]
  rrect13% 0.75x1 smd paste+0 mask+0: 1(-0.75,0) 2(0.75,0)
  silkscreen extent -0.8,-0.9 0.8,0.9
FP-VJ2225Y104KXGAT_2225-IPC_A [mil]
  rrect6% 69.04x263.98 smd paste+0 mask+0: 1(-102.19,0) 2(102.19,0)
  silkscreen extent -56,-132 56,132
FUSE_0443 [mm] "LITTELFUSE"
  rect 3.25x3.43 smd: 1(-4.675,0) 2(4.675,0)
  silkscreen extent -2.7,-1.7 2.7,1.7
GBU [mm] "Comchip / Diodes Inc diode bridge"
  round 2 hole 1.5: 1(-7.62,0) 2(-2.54,0) 3(2.54,0) 4(7.62,0)
  silkscreen extent -11.15,-2.28 11.15,1.28
Harwin_D3082-05 [mm] "Shorting Plug, 10.16mm spacing, TH"
  round 1.8 hole 1.3: 1(-5.08,0) 2(5.08,0)
  silkscreen extent -3.9,-0.53 3.9,0.53
IEC_HighVoltage_Small [mil]
  silkscreen extent -107,-88 107,97
IEC_HotSurface_Small [mil]
  silkscreen extent -107,-93 107,92
Keystone5000 [mil] "For Keystone 500x miniature loop terminals"
  round 80 hole 40: 1(0,0)
  silkscreen extent -52,-52 52,52
Keystone5001 [mil] "For Keystone 500x miniature loop terminals"
  round 80 hole 40: 1(0,0)
  silkscreen extent -52,-52 52,52
Keystone5002 [mil] "For Keystone 500x miniature loop terminals"
  round 80 hole 40: 1(0,0)
  silkscreen extent -52,-52 52,52
Keystone5009 [mil] "Keystone Compact loops"
  round 87 hole 63: 1(0,0)
  silkscreen extent -70,-70 70,70
Keystone24438 [mil] "Standoff, Aluminium, M3x0.5mm, L 25 mm"
  round 1 on Mech4: 0(0,0)
LED_LTST-C170_Red [mm] "LITE-ON"
  rect 1.2x1.2 smd: 1(-1.05,0) 2(1.05,0)
  silkscreen extent -1.6,-1 2.2,1
LTST-C170KFKT_Orange [mm] "LITE-ON"
  rect 1.2x1.2 smd: 1(-1.05,0) 2(1.05,0)
  silkscreen extent -1.6,-1 2.2,1
LTST-C170KGKT_Green [mm] "LITE-ON"
  rect 1.2x1.2 smd: 1(-1.05,0) 2(1.05,0)
  silkscreen extent -1.6,-1 2.2,1
MTGP_M3_PanHead [mm] "M3Mounting Hole, Plated, for Pan Head"
  round 6.8 hole 3.3: 1(0,0)
Net-Tie_10mil [mil] "10mil net tie, no solder mask opening, no solder paste"
  rect 10x10 smd paste-5 mask+0: 1(-10,0) 2(10,0)
Net-Tie_10milWide_30milLong#1 [mil] "10mil net tie, no solder mask opening, no solder paste"
  rect 30x10 smd paste-5 mask+0: 1(-15,0) 2(15,0)
Net-Tie_10milWide_30milLong#2 [mil] "10mil net tie, no solder mask opening, no solder paste"
  rect 30x10 smd paste-5 mask-5: 1(-15,0) 2(15,0)
Net-Tie_50milWide_30milLong [mil] "50mil net tie, no solder mask opening, no solder paste"
  rect 30x50 smd paste-20 mask+0: 1(-15,0) 2(15,0)
On-Shore_OSTVN02A150 [mm] "Terminal Block, 2.54mm, 2-pole, Brass, TH"
  rect 1.8x1.8 hole 1.3: 1(-1.27,0)
  round 1.8 hole 1.3: 2(1.27,0)
  silkscreen extent -3.1,-3.25 2.77,3.25
Phoenix_1792892 [mm] "Terminal Block, 5mm, 5x1, R/A, TH"
  rrect50% 1.7x1.7 hole 1.2: 1(-10,0)
  round 1.7 hole 1.2: 2(-5,0) 3(0,0) 4(5,0) 5(10,0)
  silkscreen extent -12.8,-4.95 12.5,5.55
Phoenix_1904150 [mm] "TH, 3-Leads, Body 28.56x16mm, Pitch 9.52mm"
  rect 1.8x1.8 hole 1.3: 1(-9.52,3.1)
  round 1.8 hole 1.3: 2(0,3.1) 3(9.52,3.1)
  silkscreen extent -14.8,-8 14.85,8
